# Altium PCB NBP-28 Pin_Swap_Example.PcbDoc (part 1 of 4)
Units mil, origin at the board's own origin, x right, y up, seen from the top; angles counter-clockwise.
Board outline 2716.54 x 4967.15 mil, 10 copper layers (Top Layer, Mid-Layer 1, VCC1V2, Mid-Layer 2, VCC, GND, MidLayer4, VCCINT, Mid-Layer 3, Bottom Layer), stack 81 mil thick; 254 components, 445 nets, 1667 pads, 770 vias.
Unrouted connection lines stored in the file: 611.
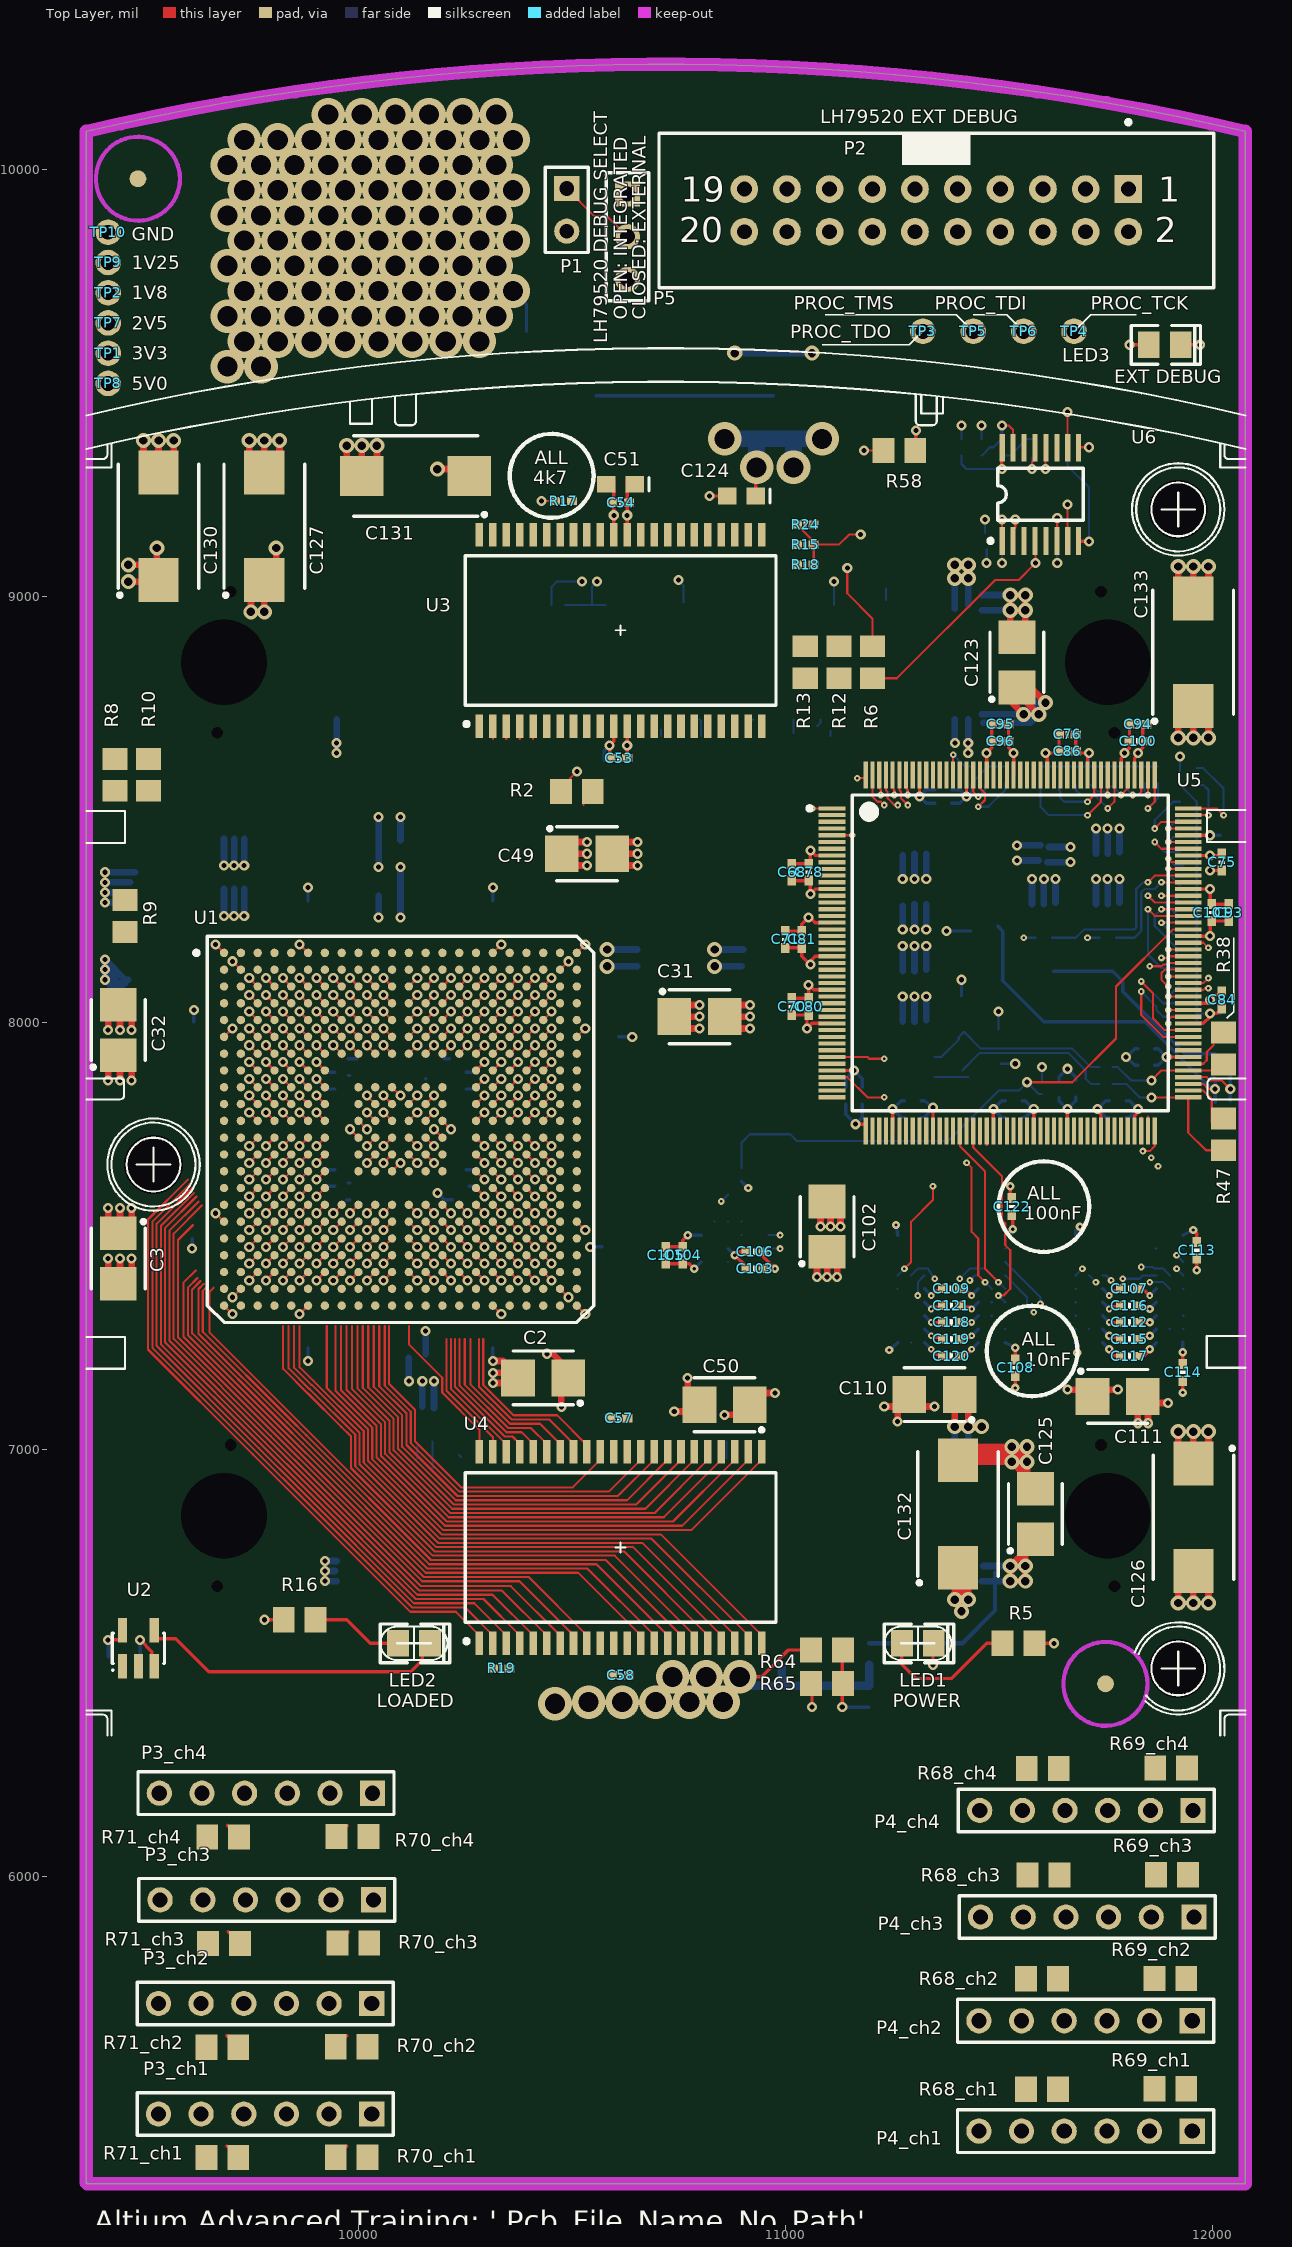
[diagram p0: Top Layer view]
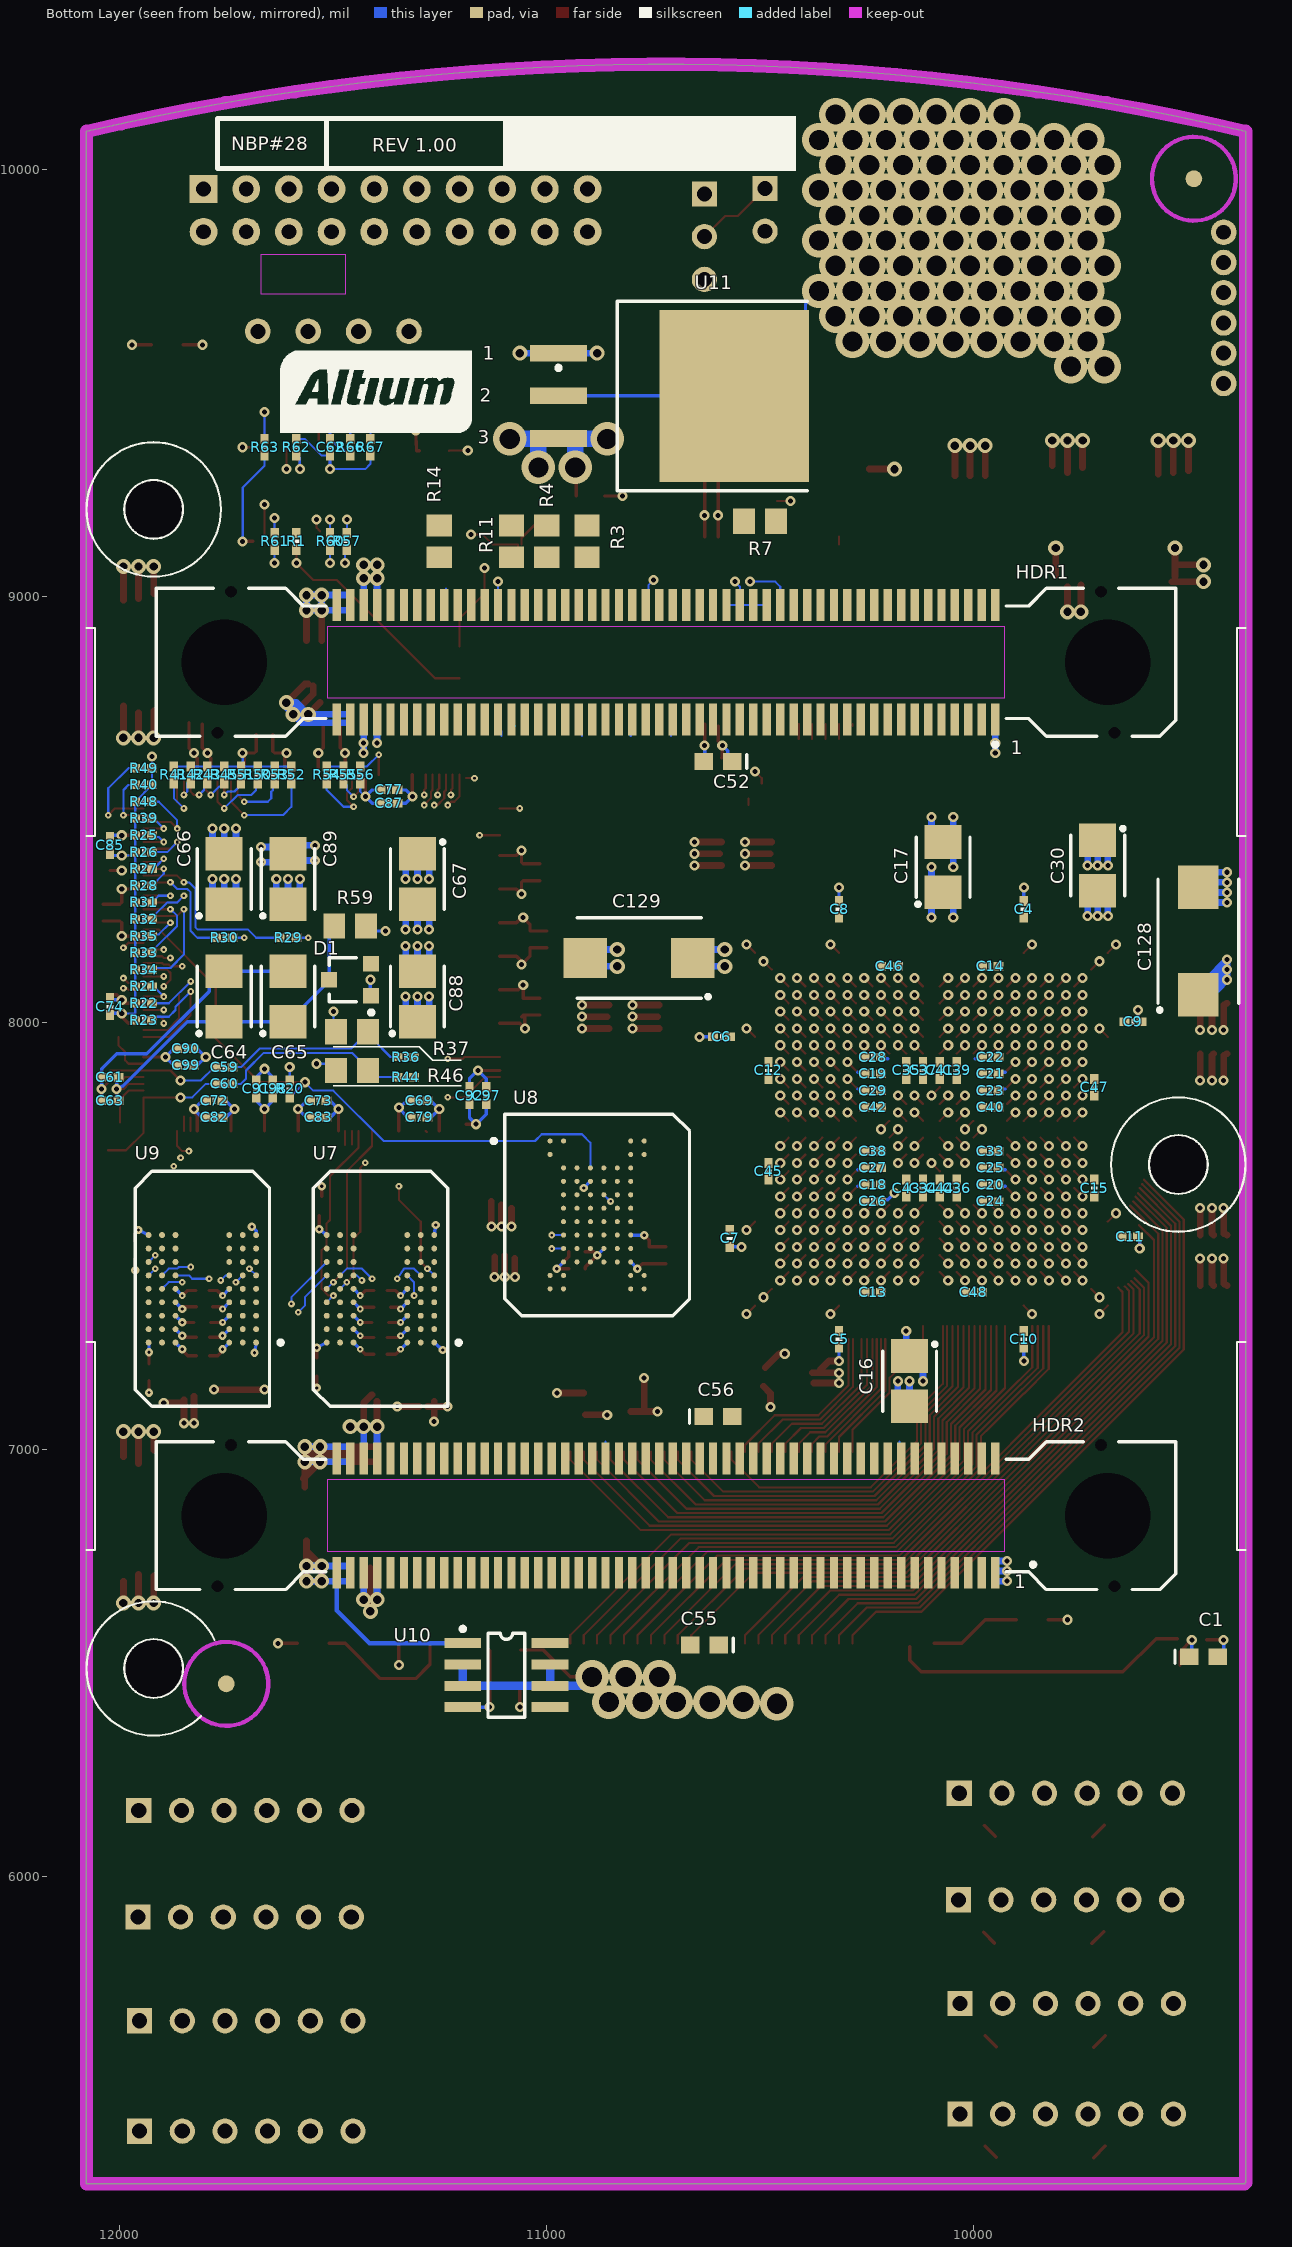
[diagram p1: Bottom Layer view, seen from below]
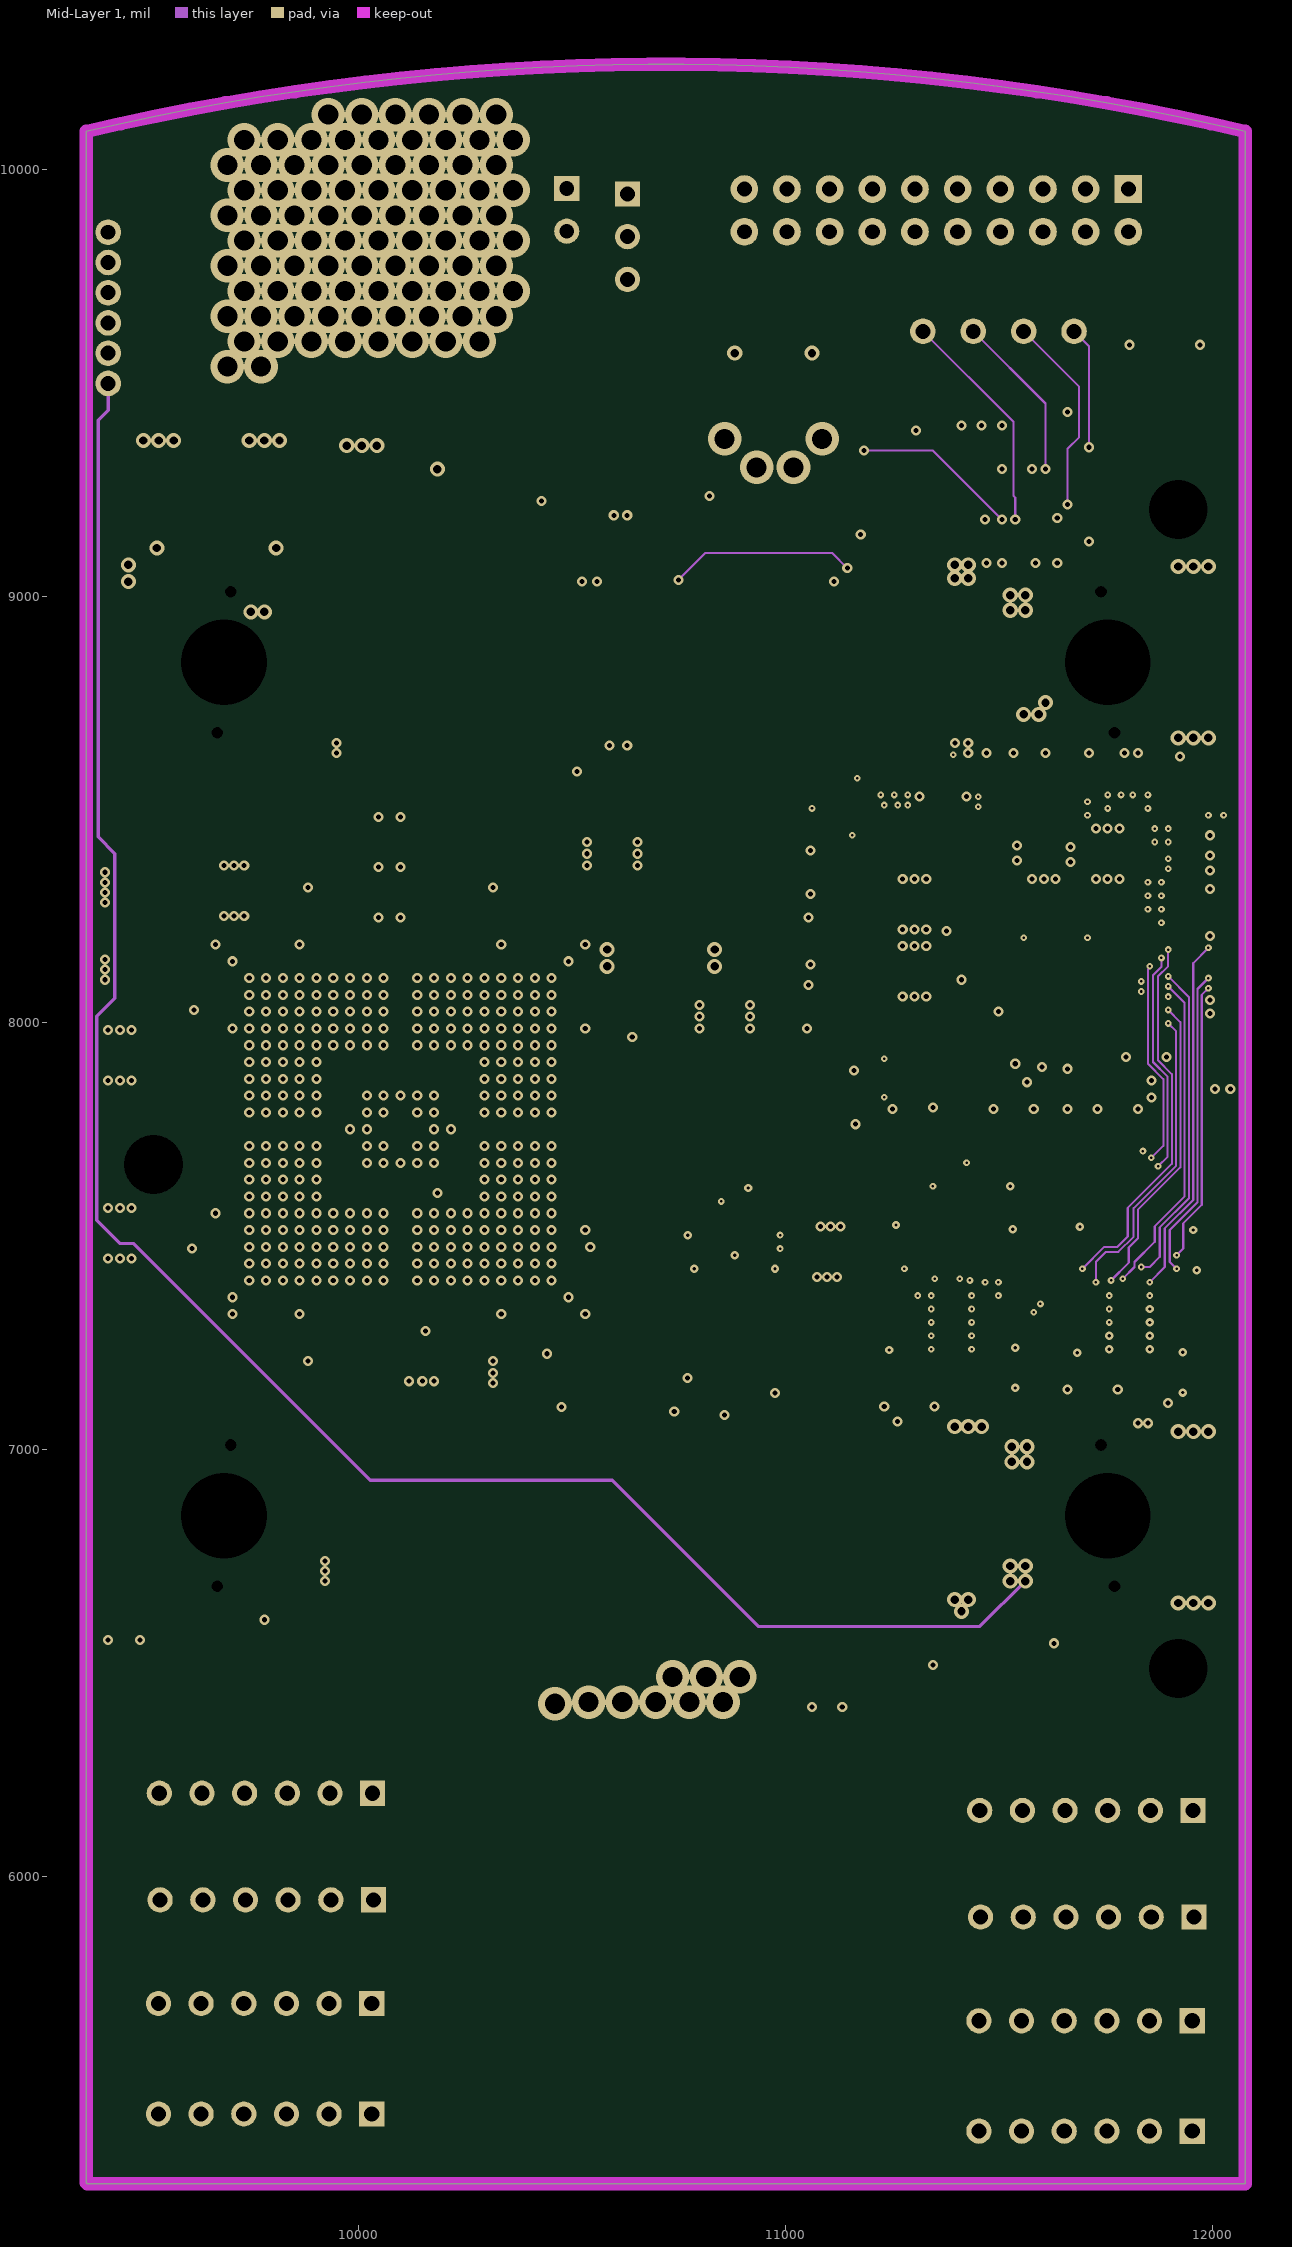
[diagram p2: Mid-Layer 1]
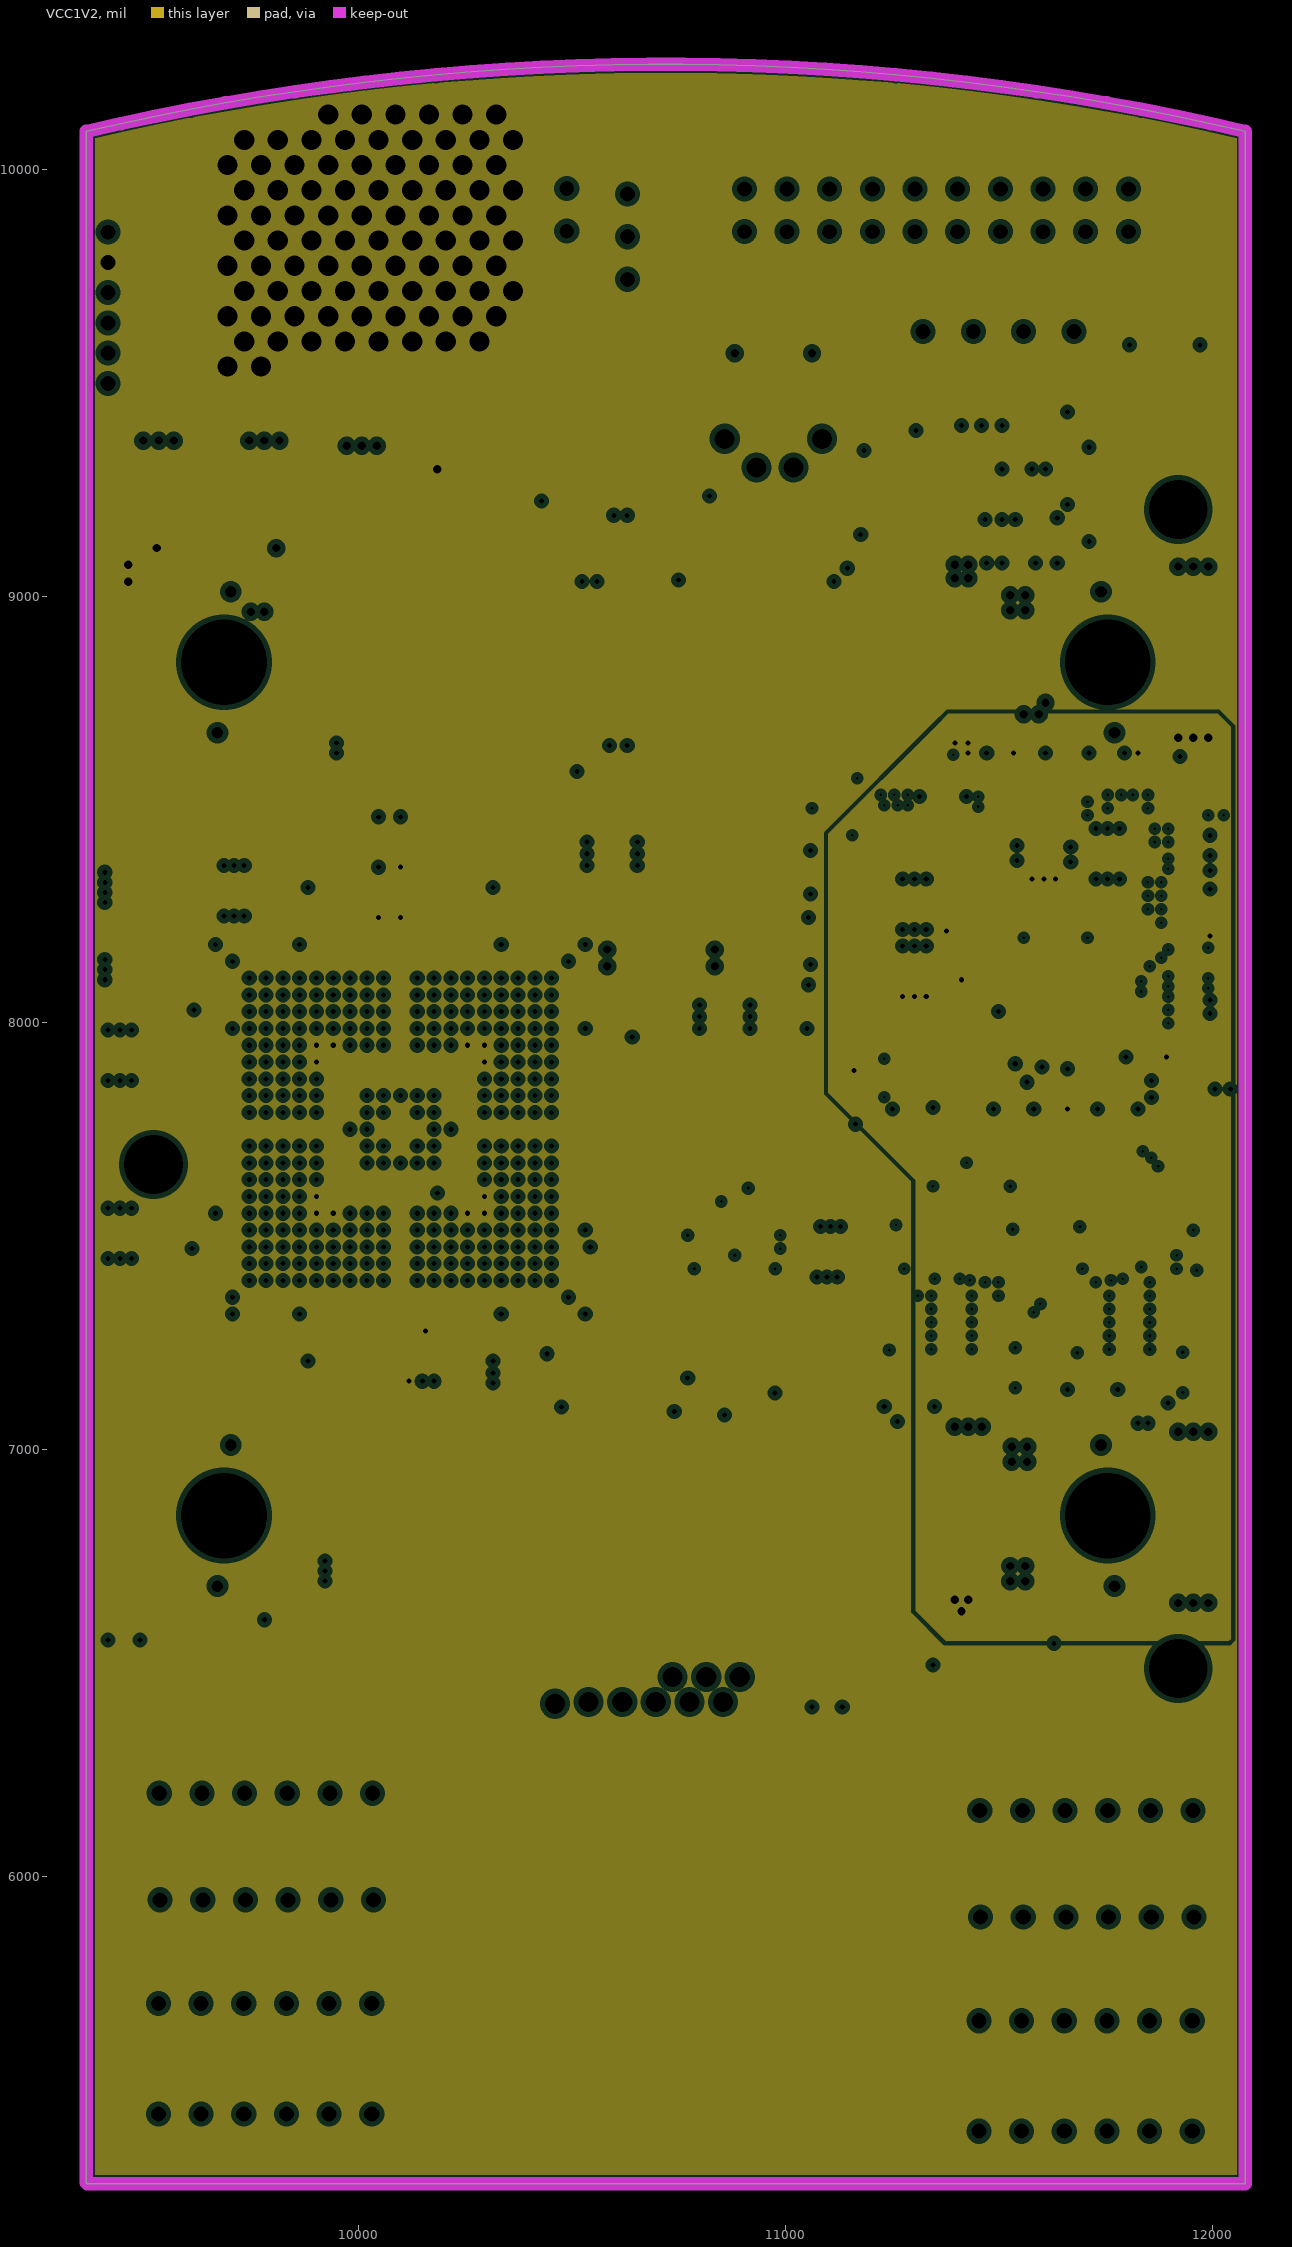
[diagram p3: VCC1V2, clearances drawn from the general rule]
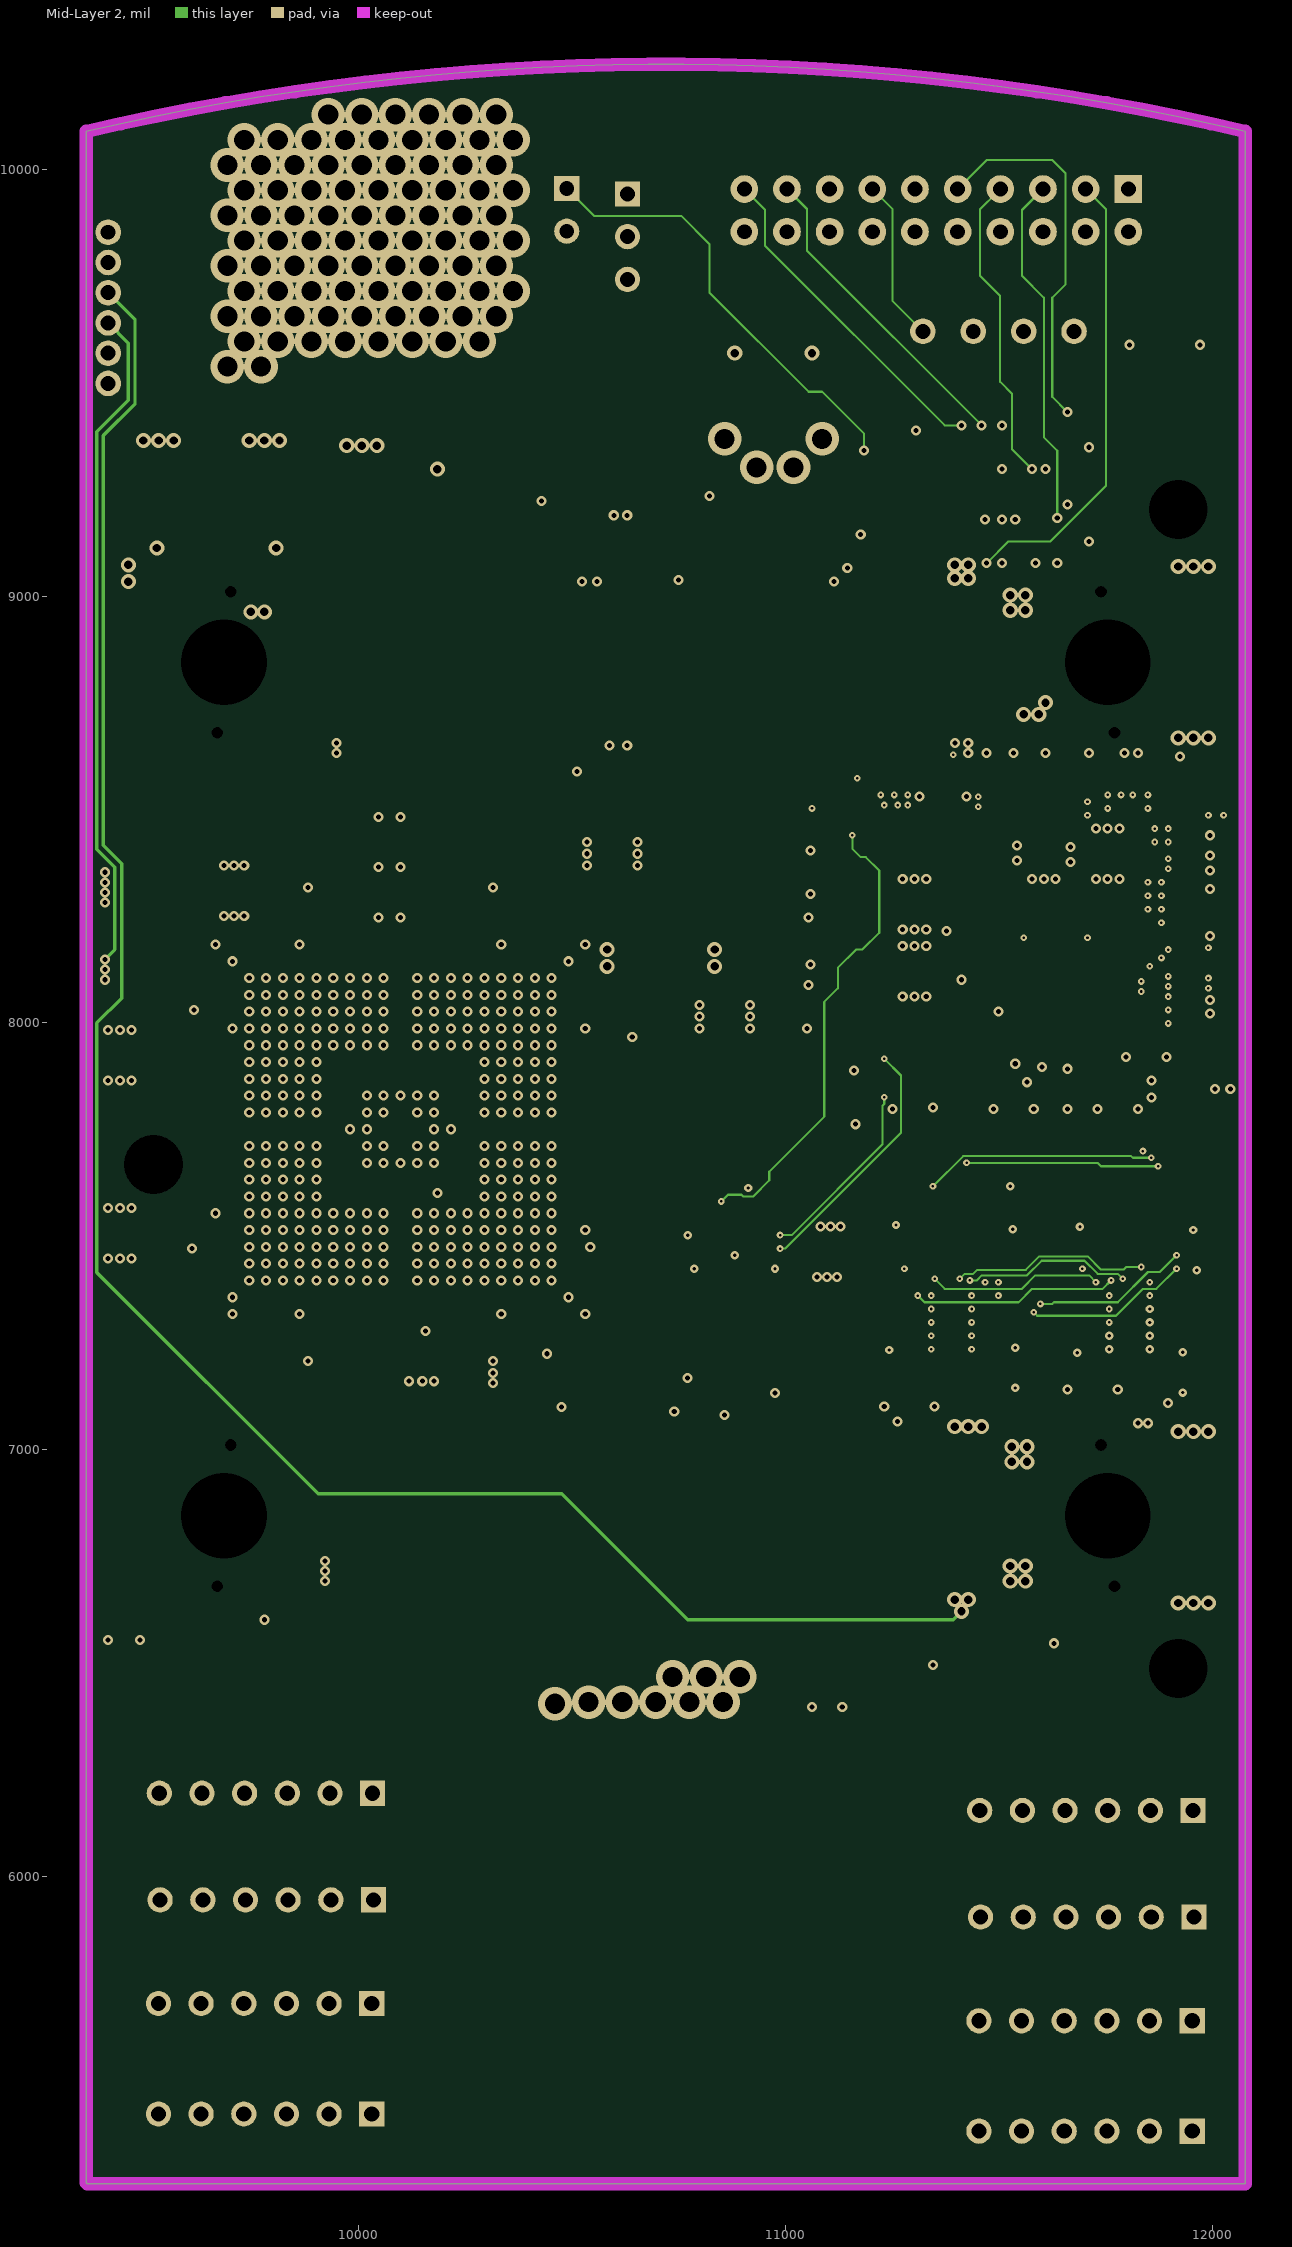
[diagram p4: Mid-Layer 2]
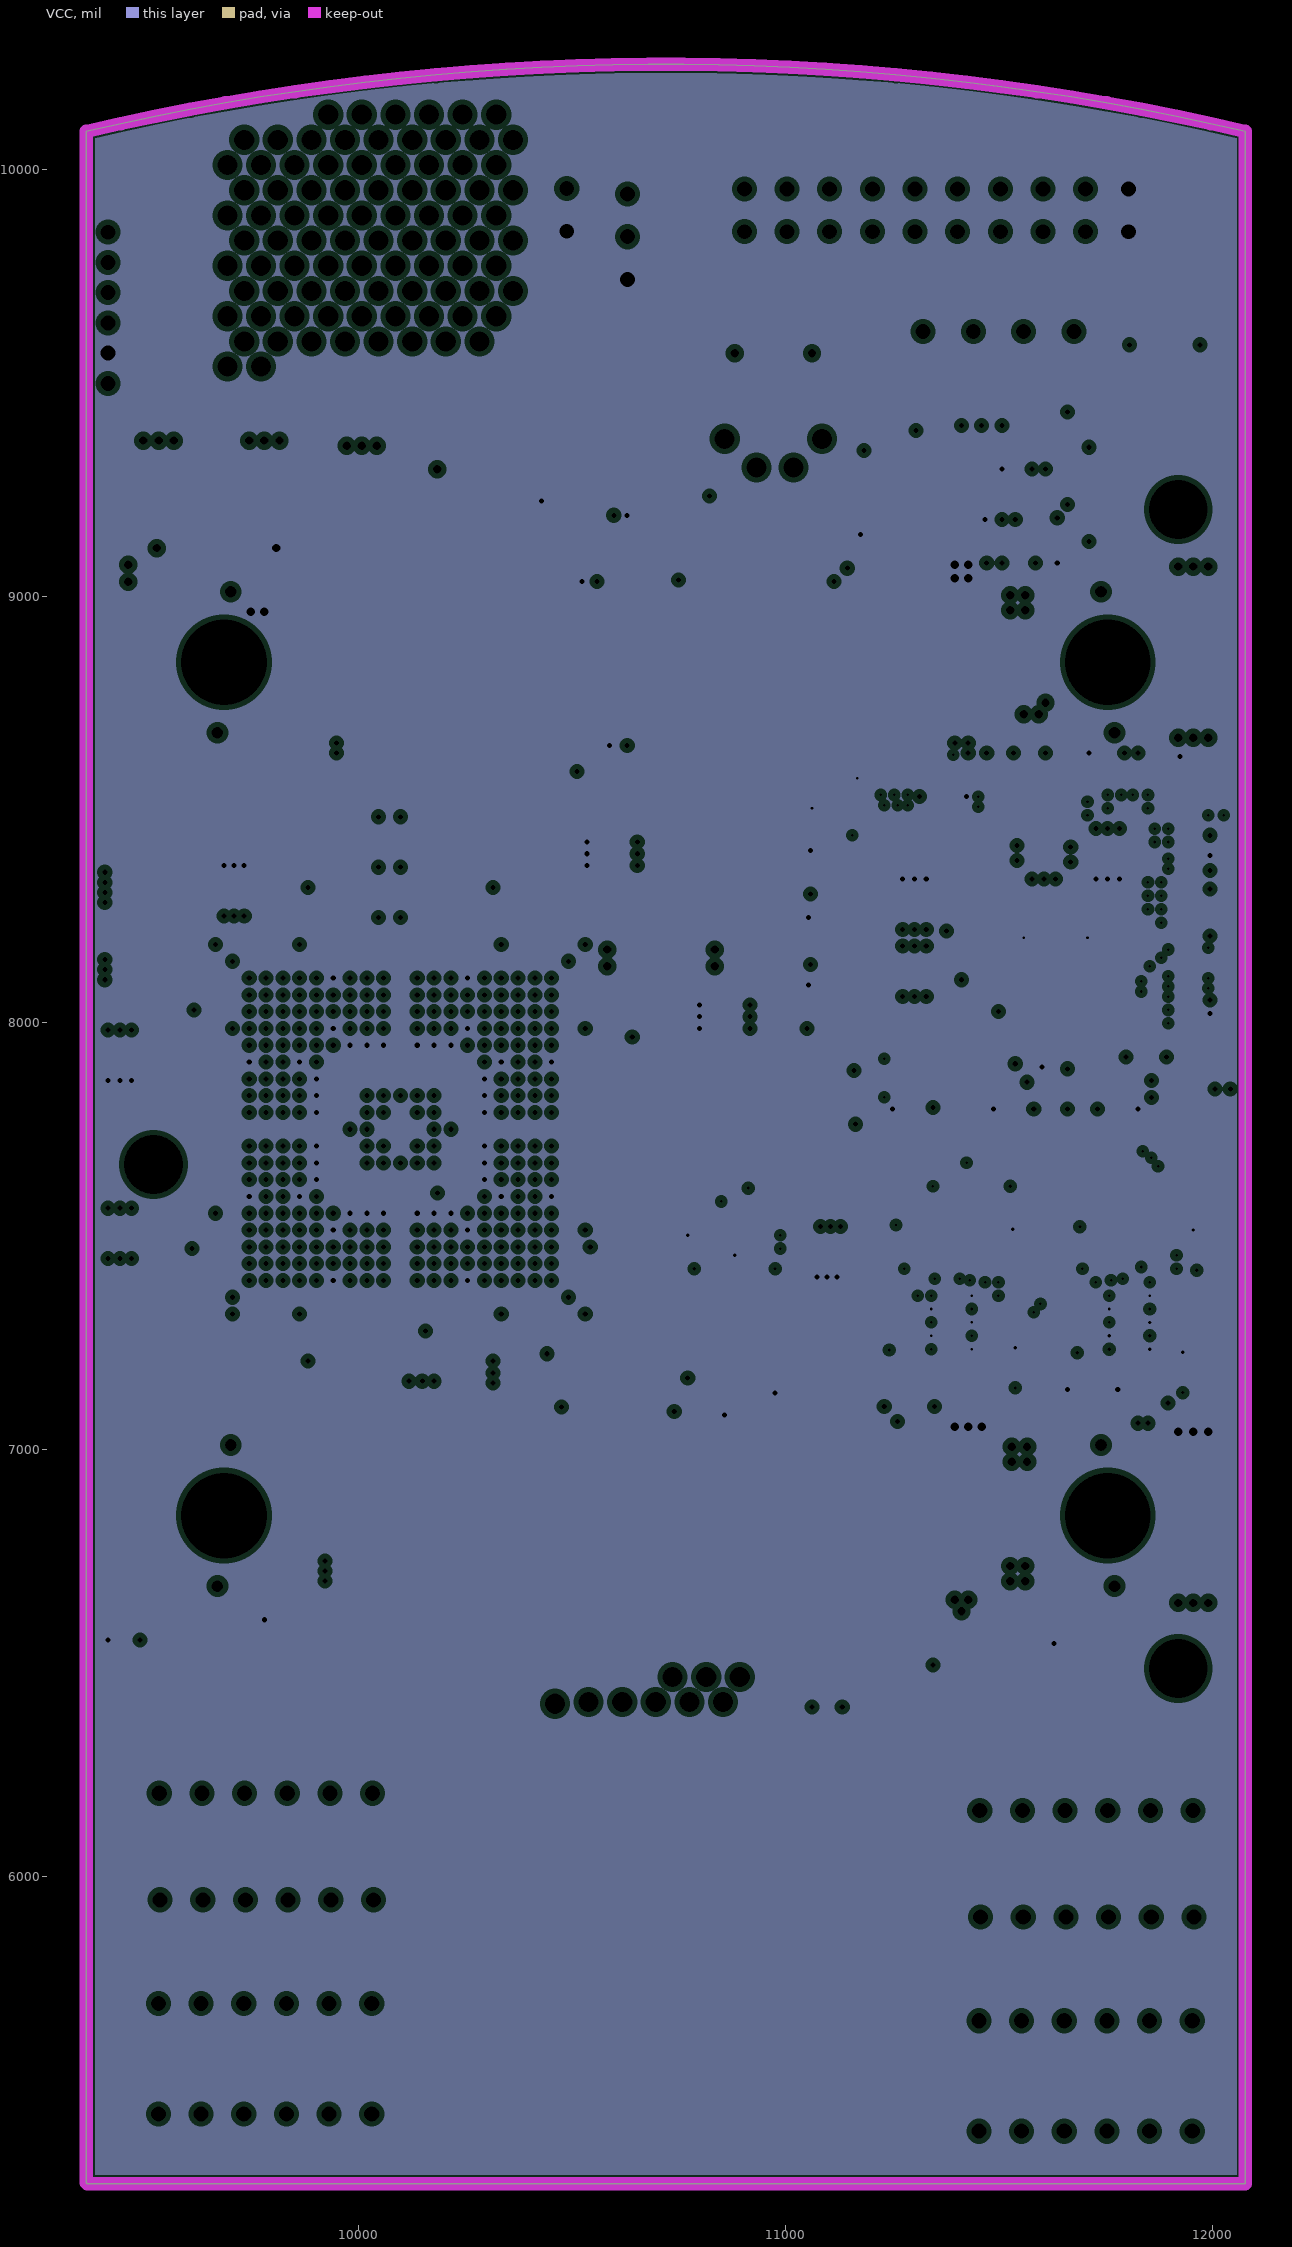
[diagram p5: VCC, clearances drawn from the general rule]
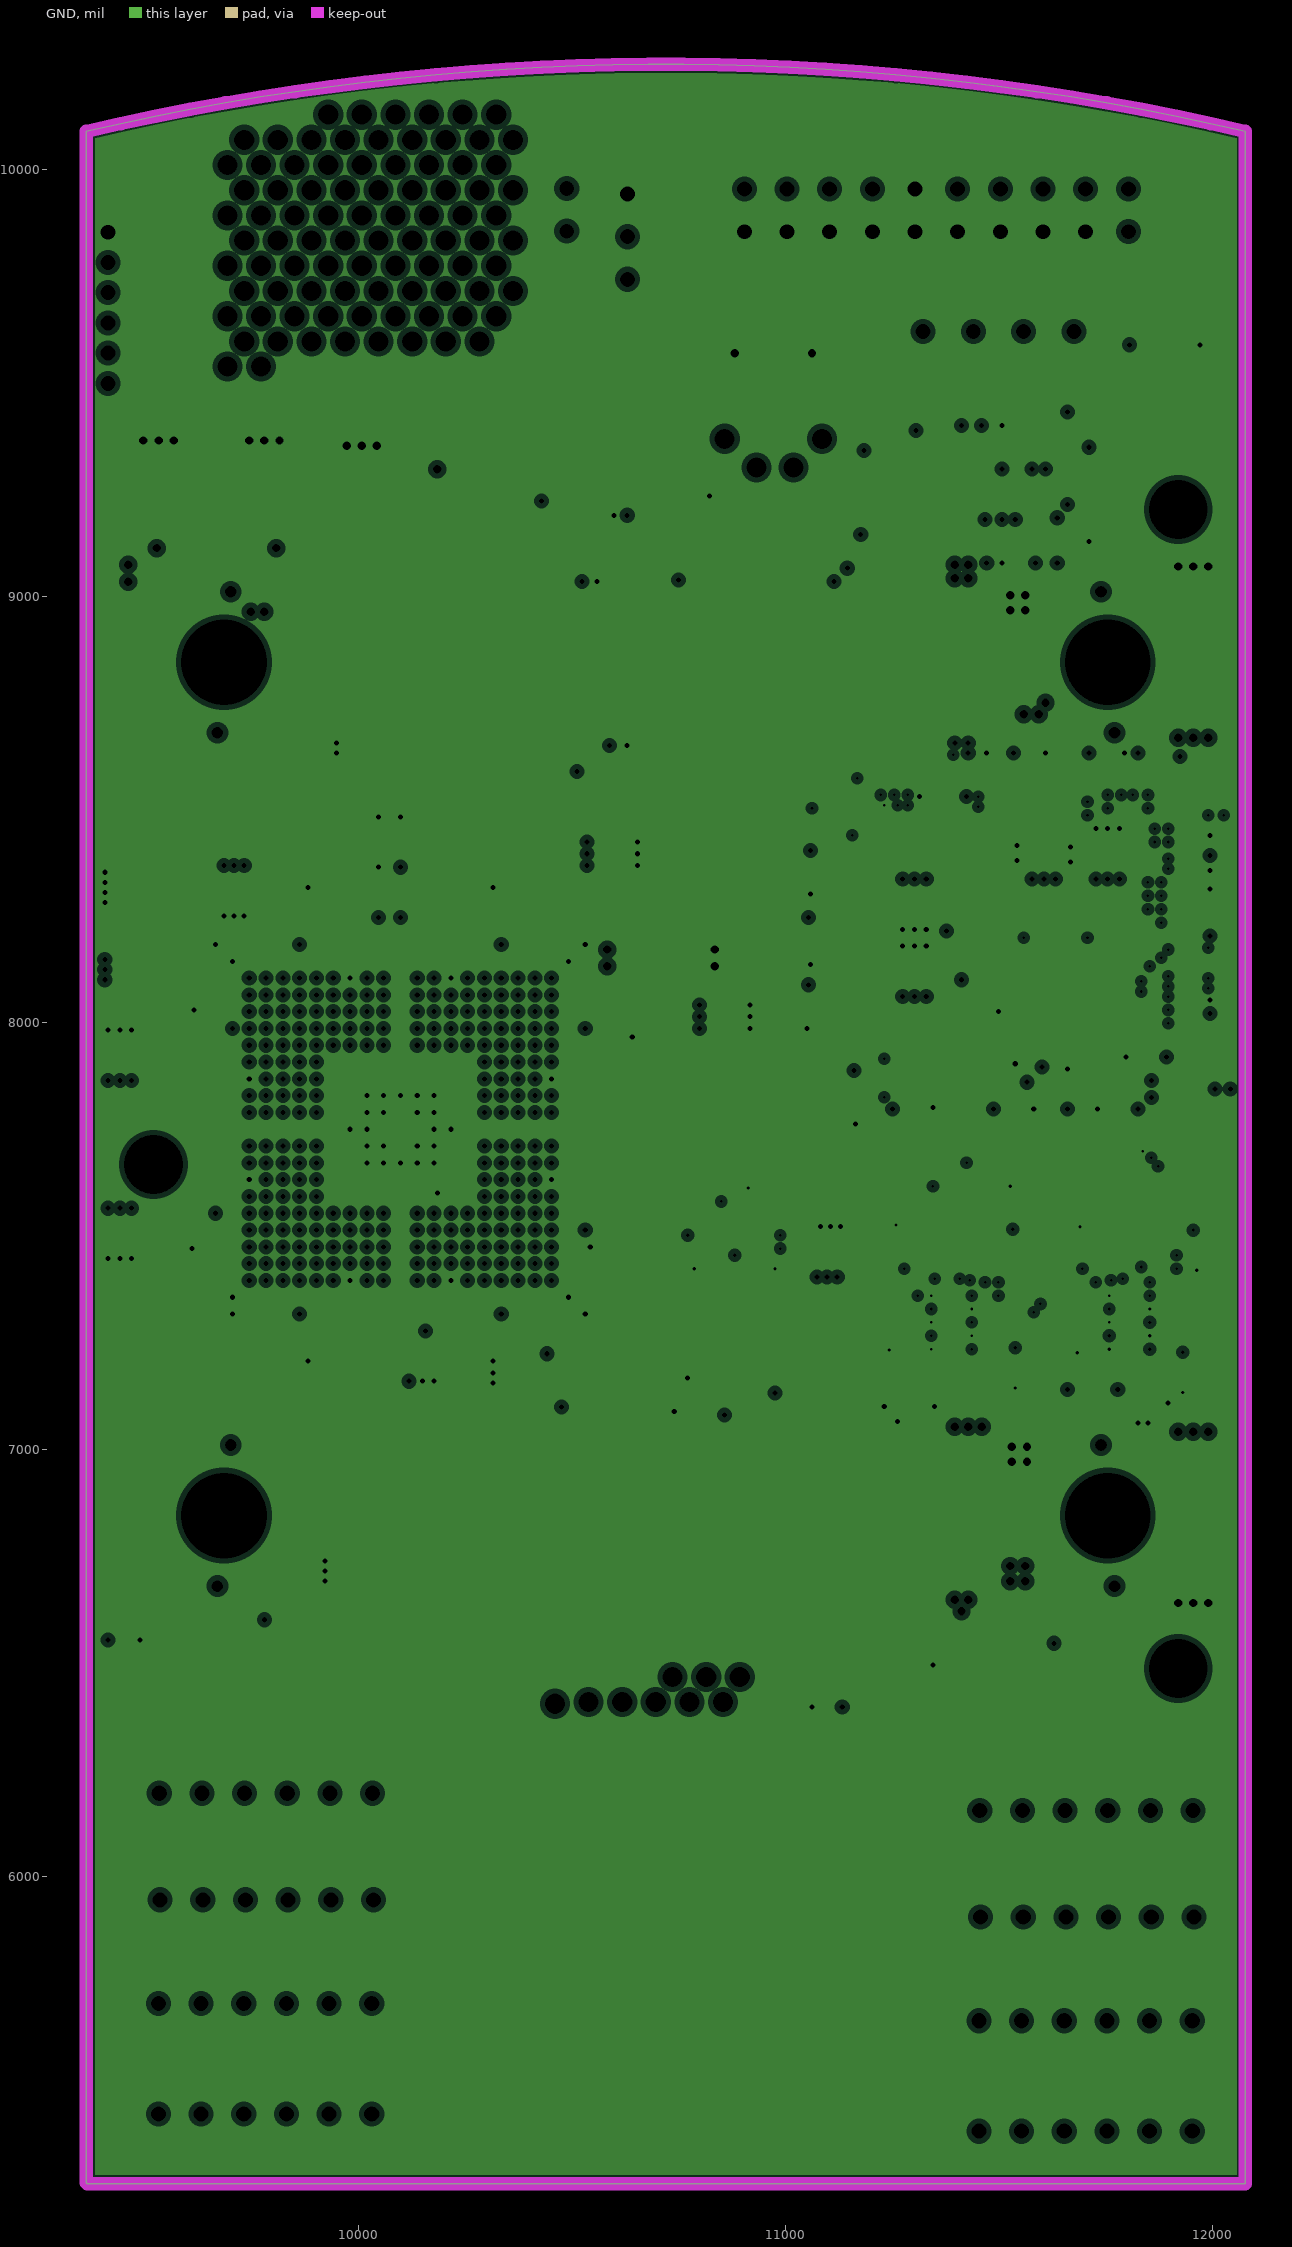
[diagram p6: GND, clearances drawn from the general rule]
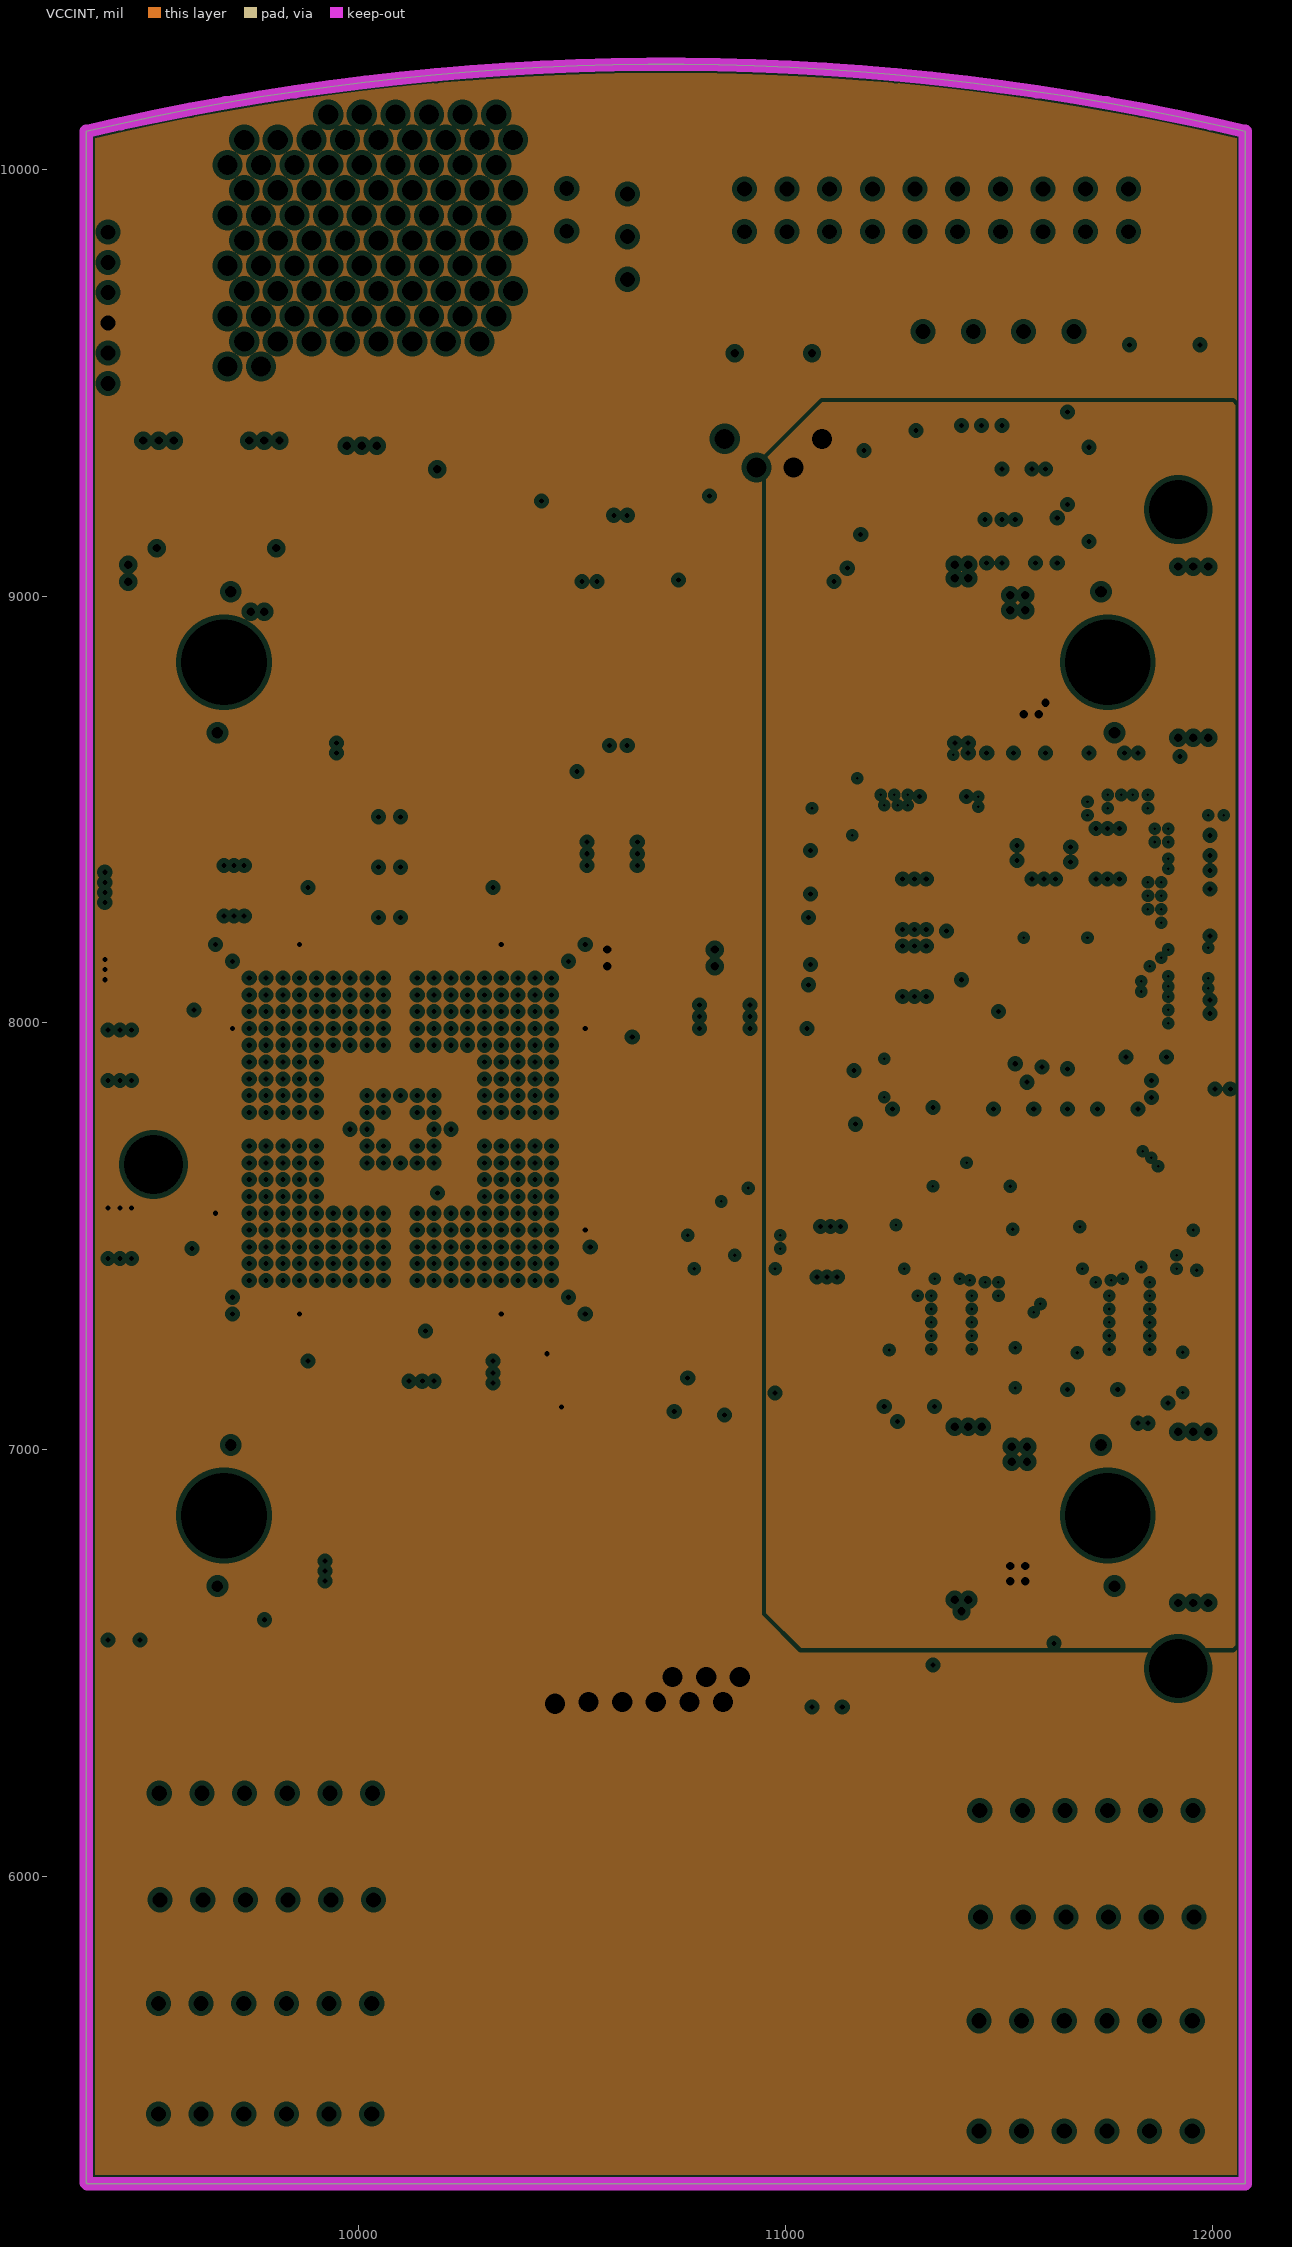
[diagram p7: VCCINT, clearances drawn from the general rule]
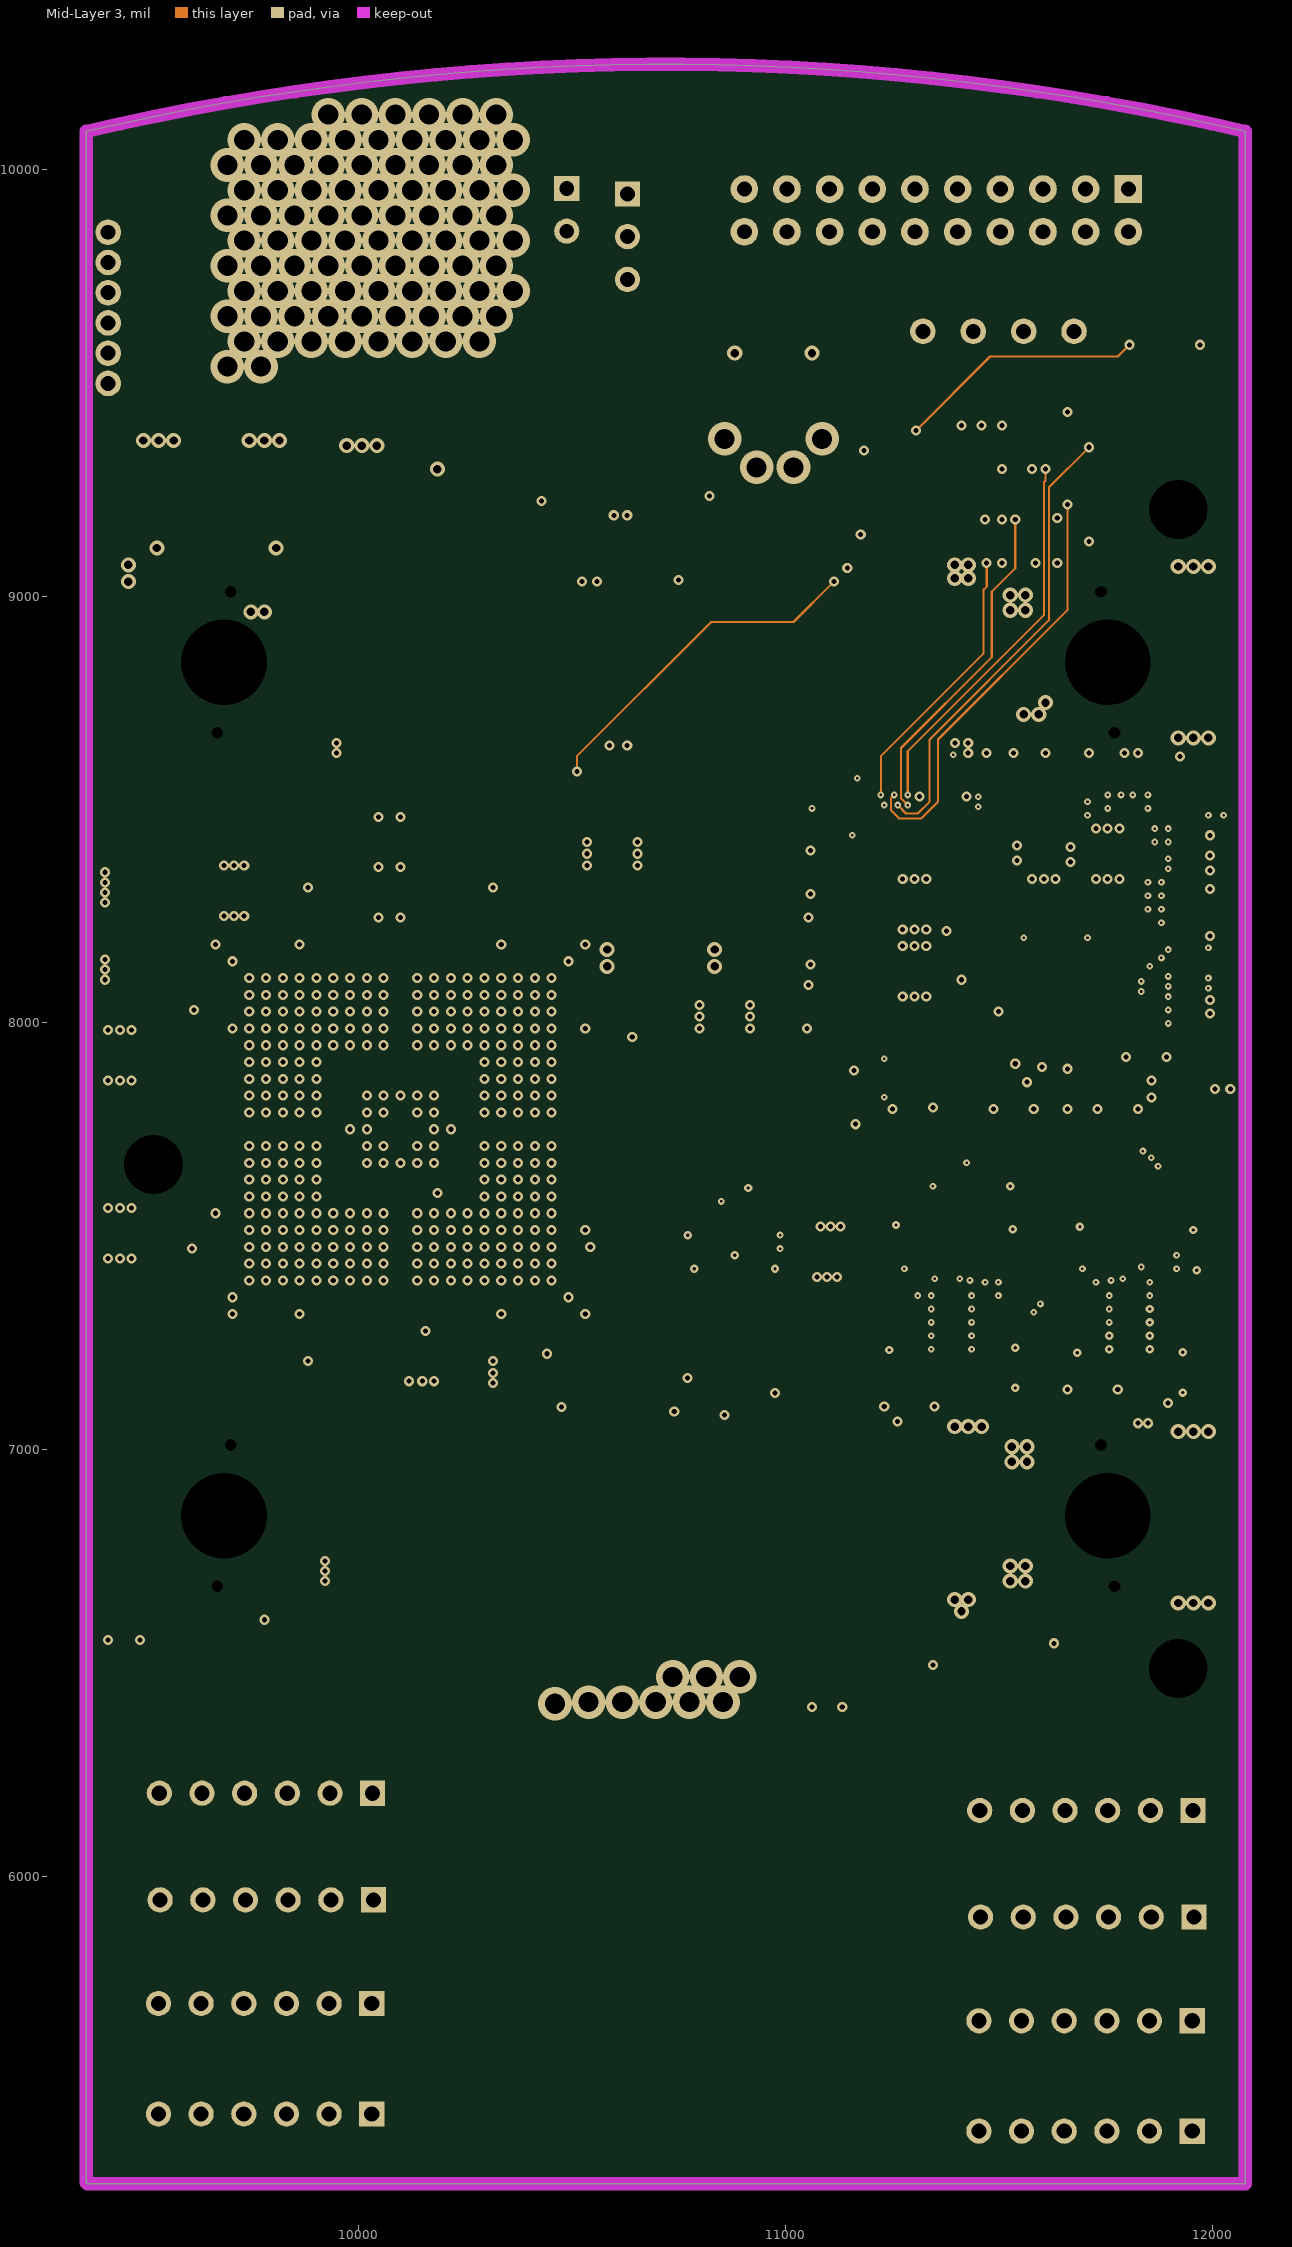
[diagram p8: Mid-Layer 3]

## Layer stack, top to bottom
Top Solder: solder mask 0.4, Solder Resist, Dk 3.5
Top Layer: signal copper 1.4
Dielectric1: core 7, FR-4, Dk 4.8
Mid-Layer 1: signal copper 1.4
Dielectric2: prepreg 8, FR-4, Dk 4.8
VCC1V2: plane copper 1.4, net (Multiple Nets)
Dielectric9: core 7, FR-4, Dk 4.8
Mid-Layer 2: signal copper 1.4
Dielectric3: prepreg 8, FR-4, Dk 4.8
VCC: plane copper 1.4, net VCC3V3
Dielectric8: core 7, FR-4, Dk 4.8
GND: plane copper 1.4, net GND
Dielectric6: prepreg 8, FR-4, Dk 4.8
MidLayer4: signal copper 1.4
Dielectric5: core 7, FR-4, Dk 4.8
VCCINT: plane copper 1.4, net (Multiple Nets)
Dielectric7: prepreg 8, FR-4, Dk 4.8
Mid-Layer 3: signal copper 1.4
Dielectric4: core 7, FR-4, Dk 4.8
Bottom Layer: signal copper 1.4
Bottom Solder: solder mask 0.4, Solder Resist, Dk 3.5

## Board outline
9361.68,5281.7 9361.68,10089.55 cw(c10719.92,4309.99) 12078.19,10089.54 12078.22,10089.55 12078.22,5279.7 9363.68,5279.7

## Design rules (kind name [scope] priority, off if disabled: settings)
Clearance "LQFP Clearance" [isPad and InComponent(U5) vs isPad and InComponent(U5)] p1: gap=5.91 ignorepadtopadclearanceinfootprint=FALSE except(0: Arc-Hole Track-Hole SMDPad-Hole THPad-Hole Via-Hole Fill-Hole Poly-Hole Region-Hole Text-Hole)
Clearance Clearance_Polygons [InPolygon] p2: gap=11.81 ignorepadtopadclearanceinfootprint=FALSE except(0: Arc-Hole Track-Hole SMDPad-Hole THPad-Hole Via-Hole Fill-Hole Poly-Hole Region-Hole Text-Hole)
Clearance "InnerLayer Track-Via Clearance" [OnMid And IsTrack vs IsVia] p3: gap=5 ignorepadtopadclearanceinfootprint=FALSE except(0: Arc-Hole Track-Hole SMDPad-Hole THPad-Hole Via-Hole Fill-Hole Poly-Hole Region-Hole Text-Hole)
Clearance "Via-Via Clearance" [IsVia vs IsVia] p4: gap=7.87 ignorepadtopadclearanceinfootprint=FALSE except(0: Arc-Hole Track-Hole SMDPad-Hole THPad-Hole Via-Hole Fill-Hole Poly-Hole Region-Hole Text-Hole)
Clearance "Pad-Pad Clearance Same Net" [IsPad vs IsPad] p5: gap=10 ignorepadtopadclearanceinfootprint=FALSE except(0: Arc-Hole Track-Hole SMDPad-Hole THPad-Hole Via-Hole Fill-Hole Poly-Hole Region-Hole Text-Hole)
Clearance "Via-Pad Clearance" [IsVia vs IsPad] p6: gap=5 ignorepadtopadclearanceinfootprint=FALSE except(0: Arc-Hole Track-Hole SMDPad-Hole THPad-Hole Via-Hole Fill-Hole Poly-Hole Region-Hole Text-Hole)
Clearance "General Clearance" [All] p7: gap=5 ignorepadtopadclearanceinfootprint=FALSE except(0: Arc-Hole Track-Hole SMDPad-Hole THPad-Hole Via-Hole Fill-Hole Poly-Hole Region-Hole Text-Hole)
ComponentClearance [All] p1 off: gap=7.87 collisioncheckmode=3 verticalgap=10 showdistances=FALSE
DiffPairsRouting [All] p1: maxlimit=10 minlimit=10 mostfreqgap=10 toplayer_minwidth=15 toplayer_maxwidth=15 toplayer_prefwidth=15 midlayer1_minwidth=15 midlayer1_maxwidth=15 midlayer1_prefwidth=15 midlayer2_minwidth=15 midlayer2_maxwidth=15 midlayer2_prefwidth=15 midlayer3_minwidth=15 midlayer3_maxwidth=15 midlayer3_prefwidth=15 midlayer4_minwidth=15 midlayer4_maxwidth=15 midlayer4_prefwidth=15 bottomlayer_minwidth=15 bottomlayer_maxwidth=15 bottomlayer_prefwidth=15 maxuncoupledlength=500
FabricationTestPointUsage TestPointUsage [All] p1 off: valid=0 allowmultiple=FALSE
FabricationTestpoint Testpoint [All] p1 off: side=3 testpointundercomponent=TRUE minsize=40 maxsize=100 preferedsize=60 minholesize=0 maxholesize=40 preferedholesize=32 testpointgrid=1 allowsidetop=TRUE allowsidebottom=TRUE usegrid=TRUE gridtolerance=0.01
HoleSize [All] p1: absolutevalues=TRUE maxlimit=204.72 minlimit=5.91 maxpercent=80.000 minpercent=20.000
MinimumSolderMaskSliver [All] p1: minsoldermaskwidth=5
PlaneClearance [All] p1: clearance=11.81
PlaneConnect [All] p1: planeconnectstyle=Direct reliefexpansion=19.68 reliefentries=4 reliefconductorwidth=9.84 reliefairgap=9.84
PolygonConnect "PolygonConnect - High Current" [InNet('+5V') or InNet(VCC2V5)] p1: connectstyle=Direct reliefconductorwidth=10 reliefentries=4 polygonreliefangle="90 Angle" airgapwidth=10
PolygonConnect "PolygonConnect - Heatsink" [(HasFootprint('TO-263') AND InNet('VCC1V2'))] p2: connectstyle=Direct reliefconductorwidth=10 reliefentries=4 polygonreliefangle="90 Angle" airgapwidth=10
PolygonConnect [All] p3: connectstyle=Relief reliefconductorwidth=11.81 reliefentries=4 polygonreliefangle="90 Angle" airgapwidth=10
RoomDefinition ch1 [InComponentClass('ch1')] p1: confinementstyle=ConfineIn formatcopy=TRUE lockcomponents=FALSE outline 9402.11,5304.34 12053.01,5304.34 12053.01,5538.53 9402.11,5538.53
RoomDefinition ch2 [InComponentClass('ch2')] p2: confinementstyle=ConfineIn formatcopy=TRUE lockcomponents=FALSE outline 9402.11,5554.93 12053.01,5554.93 12053.01,5800.27 9402.11,5800.27
RoomDefinition ch3 [InComponentClass('ch3')] p3: confinementstyle=ConfineIn formatcopy=TRUE lockcomponents=FALSE outline 9406.05,5805.52 12056.94,5805.52 12056.94,6039.71 9406.05,6039.71
RoomDefinition ch4 [InComponentClass('ch4')] p4: confinementstyle=ConfineIn formatcopy=TRUE lockcomponents=FALSE outline 9404.08,6056.11 12054.98,6056.11 12054.98,6290.3 9404.08,6290.3
RoutingVias [All] p1: holewidth=11.81 width=23.62 viastyle="Through Hole" minholewidth=5.91 minwidth=15.75 maxholewidth=28 maxwidth=50
SilkToSolderMaskClearance SilkscreenOverComponentPads [IsPad] p1: minsilkscreentomaskgap=5 clearancetoexposedcopper=TRUE
SolderMaskExpansion SolderMaskExpansion_0402 [HasFootprint('CC1005-0402')] p1: expansion=2.95 istentingtop=FALSE
SolderMaskExpansion SolderMaskExpansion_Vias [IsVia] p2: expansion=-25.59 istentingtop=FALSE
SolderMaskExpansion [All] p3: expansion=3.94 istentingtop=FALSE
SupplyNets SupplyNets_GND [InNet('GND')] p1: voltage=0,000
SupplyNets SupplyNets_3V3 [InNet('VCC3V3')] p2: voltage=3,000
SupplyNets SupplyNets_2V5 [InNet('VCC2V5')] p3: voltage=2,000
SupplyNets SupplyNets_1V8 [InNet('VCC1V8')] p4: voltage=1,000
SupplyNets SupplyNets_1V2 [InNet('VCC1V2')] p5: voltage=1,000
SupplyNets SupplyNets_5V [InNet('+5V')] p6: voltage=5,000
Width [All] p1: maxlimit=98.42 minlimit=5 preferedwidth=5
21 further rules are at their usual default settings.

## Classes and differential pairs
channel class Multi-channel_diff-pairs: ch1 ch2 ch3 ch4
component class ch1: P3_ch1 P4_ch1 R68_ch1 R69_ch1 R70_ch1 R71_ch1
component class ch2: P3_ch2 P4_ch2 R68_ch2 R69_ch2 R70_ch2 R71_ch2
component class ch3: P3_ch3 P4_ch3 R68_ch3 R69_ch3 R70_ch3 R71_ch3
component class ch4: P3_ch4 P4_ch4 R68_ch4 R69_ch4 R70_ch4 R71_ch4
component class TOP_SHEET: C123 C124 C125 C126 C127 C128 C129 C130 C131 C132 C133 R64 R65 TP7 TP8 TP9 TP10 U10 U11
component class U_FPGA_RAM: C49 C50 C51 C52 C53 C54 C55 C56 C57 C58 U3 U4
component class U_FPGA: C1 C2 C3 C4 C5 C6 C7 C8 C9 C10 C11 C12 C13 C14 C15 C16 C17 C18 C19 C20 C21 C22 C23 C24 C25 C26 C27 C28 C29 C30 C31 C32 C33 C34 C35 C36 C37 C38 C39 C40 C41 C42 C43 C44 C45 C46 C47 C48 HDR1 HDR2 LED1 LED2 R1 R2 R3 R4 R5 R6 R7 R8 R9 R10 R11 R12 R13 R14 R15 R16 R17 R18 R19 TP1 TP2 U1 U2
component class U_PROCESSOR_MEMORIES: C102 C103 C104 C105 C106 C107 C108 C109 C110 C111 C112 C113 C114 C115 C116 C117 C118 C119 C120 C121 C122 U7 U8 U9
component class U_PROCESSOR: C59 C60 C61 C62 C63 C64 C65 C66 C67 C68 C69 C70 C71 C72 C73 C74 C75 C76 C77 C78 C79 C80 C81 C82 C83 C84 C85 C86 C87 C88 C89 C90 C91 C92 C93 C94 C95 C96 C97 C98 C99 C100 C101 D1 LED3 P1 P2 P5 R20 R21 R22 R23 R24 R25 R26 R27 R28 R29 R30 R31 R32 R33 R34 R35 R36 R37 R38 R39 R40 R41 R42 R43 R44 R45 R46 R47 R48 R49 R50 R51 R52 R53 R54 R55 R56 R57 R58 R59 R60 R61 R62 R63 R66 R67 TP3 TP4 TP5 TP6 U5 U6
net class A[25..0]: A0 A1 A2 A3 A4 A5 A6 A7 A8 A9 A10 A11 A12 A13 A14 A15 A16 A17 A18 A19 A20 A21 A22 A23 A24 A25
net class D[31..0]: D0 D1 D2 D3 D4 D5 D6 D7 D8 D9 D10 D11 D12 D13 D14 D15 D16 D17 D18 D19 D20 D21 D22 D23 D24 D25 D26 D27 D28 D29 D30 D31
net class INT[4..0]: INT0 INT1 INT2 INT3 INT4
net class NBLE[3..0]: NBLE0 NBLE1 NBLE2 NBLE3
net class NCS[5..0]: NCS0 NCS1 NCS2 NCS3 NCS4 NCS5
net class SDRAM_DQM[3..0]: SDRAM_DQM0 SDRAM_DQM1 SDRAM_DQM2 SDRAM_DQM3
net class SRAM0_A[18..0]: SRAM0_A0 SRAM0_A1 SRAM0_A2 SRAM0_A3 SRAM0_A4 SRAM0_A5 SRAM0_A6 SRAM0_A7 SRAM0_A8 SRAM0_A9 SRAM0_A10 SRAM0_A11 SRAM0_A12 SRAM0_A13 SRAM0_A14 SRAM0_A15 SRAM0_A16 SRAM0_A17 SRAM0_A18
net class SRAM0_D[15..0]: SRAM0_D0 SRAM0_D1 SRAM0_D2 SRAM0_D3 SRAM0_D4 SRAM0_D5 SRAM0_D6 SRAM0_D7 SRAM0_D8 SRAM0_D9 SRAM0_D10 SRAM0_D11 SRAM0_D12 SRAM0_D13 SRAM0_D14 SRAM0_D15
net class SRAM1_A[18..0]: SRAM1_A0 SRAM1_A1 SRAM1_A2 SRAM1_A3 SRAM1_A4 SRAM1_A5 SRAM1_A6 SRAM1_A7 SRAM1_A8 SRAM1_A9 SRAM1_A10 SRAM1_A11 SRAM1_A12 SRAM1_A13 SRAM1_A14 SRAM1_A15 SRAM1_A16 SRAM1_A17 SRAM1_A18
net class SRAM1_D[15..0]: SRAM1_D0 SRAM1_D1 SRAM1_D2 SRAM1_D3 SRAM1_D4 SRAM1_D5 SRAM1_D6 SRAM1_D7 SRAM1_D8 SRAM1_D9 SRAM1_D10 SRAM1_D11 SRAM1_D12 SRAM1_D13 SRAM1_D14 SRAM1_D15
differential pair DIFF_RX_ch1: +DIFF_RX_ch1_P -DIFF_RX_ch1_N
differential pair DIFF_RX_ch2: +DIFF_RX_ch2_P -DIFF_RX_ch2_N
differential pair DIFF_RX_ch3: +DIFF_RX_ch3_P -DIFF_RX_ch3_N
differential pair DIFF_RX_ch4: +DIFF_RX_ch4_P -DIFF_RX_ch4_N
differential pair DIFF_TX_ch1: +DIFF_TX_ch1_P -DIFF_TX_ch1_N
differential pair DIFF_TX_ch2: +DIFF_TX_ch2_P -DIFF_TX_ch2_N
differential pair DIFF_TX_ch3: +DIFF_TX_ch3_P -DIFF_TX_ch3_N
differential pair DIFF_TX_ch4: +DIFF_TX_ch4_P -DIFF_TX_ch4_N

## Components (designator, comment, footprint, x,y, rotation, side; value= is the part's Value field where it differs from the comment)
C1 "220nF 10V" CAPC1608 9460.11,6514.74 r180 bottom
C2 "10uF 16V" CAPC3528 10432.55,7168.29 r180 top
C3 "10uF 16V" CAPC3528 9436.48,7447.81 r270 top
C4 "0.1uF 16V" CAPC1005 9881.37,8266.71 r90 bottom
C5 "0.1uF 16V" CAPC1005 10314.44,7258.84 r270 bottom
C6 "10nF 16V" CAPC1005 10590.03,7967.5 r0 bottom
C7 "10nF 16V" CAPC1005 10570.34,7495.06 r270 bottom
C8 "10nF 16V" CAPC1005 10314.44,8266.71 r90 bottom
C9 "10nF 16V" CAPC1005 9625.46,8002.93 r180 bottom
C10 "10nF 16V" CAPC1005 9881.37,7258.84 r270 bottom
C11 "10nF 16V" CAPC1005 9633.33,7499 r180 bottom
C12 "0.1uF 16V" CAPC1005 10479.79,7888.76 r270 bottom
C13 "0.1uF 16V" CAPC1005 10235.7,7369.07 r180 bottom
C14 "0.1uF 16V" CAPC1005 9960.11,8132.85 r0 bottom
C15 "0.1uF 16V" CAPC1005 9716.01,7613.17 r90 bottom
C16 "10uF 16V" CAPC3528 10149.08,7160.41 r270 bottom
C17 "10uF 16V" CAPC3528 10070.34,8365.14 r90 bottom
C18 "0.1uF 16V" CAPC1005 10235.7,7621.04 r180 bottom
C19 "0.1uF 16V" CAPC1005 10235.7,7880.89 r180 bottom
C20 "0.1uF 16V" CAPC1005 9960.11,7621.04 r0 bottom
C21 "0.1uF 16V" CAPC1005 9960.11,7880.89 r0 bottom
C22 "10nF 16V" CAPC1005 9960.11,7920.26 r0 bottom
C23 "10nF 16V" CAPC1005 9960.11,7841.52 r0 bottom
C24 "10nF 16V" CAPC1005 9960.11,7581.67 r0 bottom
C25 "10nF 16V" CAPC1005 9960.11,7660.41 r0 bottom
C26 "10nF 16V" CAPC1005 10235.7,7581.67 r180 bottom
C27 "10nF 16V" CAPC1005 10235.7,7660.41 r180 bottom
C28 "10nF 16V" CAPC1005 10235.7,7920.26 r180 bottom
C29 "10nF 16V" CAPC1005 10235.7,7841.52 r180 bottom
C30 "10uF 16V" CAPC3528 9708.14,8369.07 r270 bottom
C31 "10uF 16V" CAPC3528 10798.69,8014.74 r0 top
C32 "10uF 16V" CAPC3528 9436.48,7983.25 r90 top
C33 "0.1uF 16V" CAPC1005 9960.11,7699.78 r0 bottom
C34 "0.1uF 16V" CAPC1005 10117.59,7613.17 r90 bottom
C35 "0.1uF 16V" CAPC1005 10156.96,7888.76 r270 bottom
C36 "0.1uF 16V" CAPC1005 10038.85,7613.17 r90 bottom
C37 "10nF 16V" CAPC1005 10117.59,7888.76 r270 bottom
C38 "10nF 16V" CAPC1005 10235.7,7699.78 r180 bottom
C39 "10nF 16V" CAPC1005 10038.85,7888.76 r270 bottom
C40 "10nF 16V" CAPC1005 9960.11,7802.15 r0 bottom
C41 "0.1uF 16V" CAPC1005 10078.22,7888.76 r270 bottom
C42 "0.1uF 16V" CAPC1005 10235.7,7802.15 r180 bottom
C43 "10nF 16V" CAPC1005 10156.96,7613.17 r90 bottom
C44 "10nF 16V" CAPC1005 10078.22,7613.17 r90 bottom
C45 "10nF 16V" CAPC1005 10479.79,7652.54 r90 bottom
C46 "10nF 16V" CAPC1005 10196.33,8132.85 r180 bottom
C47 "10nF 16V" CAPC1005 9716.01,7849.39 r270 bottom
C48 "10nF 16V" CAPC1005 9999.48,7369.07 r0 bottom
C49 "10uF 16V" CAPC3528 10534.91,8396.63 r0 top
C50 "10uF 16V" CAPC3528 10857.74,7105.3 r180 top
C51 "220nF 10V" CAPC1608 10613.65,9262.78 r180 top
C52 "220nF 10V" CAPC1608 10597.9,8613.17 r0 bottom
C53 "10nF 16V" CAPC1005 10609.71,8621.04 r0 top
C54 "10nF 16V" CAPC1005 10613.65,9219.47 r180 top
C55 "220nF 10V" CAPC1608 10629.4,6542.3 r0 bottom
C56 "220nF 10V" CAPC1608 10597.9,7077.74 r180 bottom
C57 "10nF 16V" CAPC1005 10609.71,7073.8 r180 top
C58 "10nF 16V" CAPC1005 10613.65,6471.44 r0 top
C59 "0.1uF 16V" CAPC1005 11755.38,7896.63 r0 bottom
C60 "0.1uF 16V" CAPC1005 11755.38,7857.26 r0 bottom
C61 "10nF 16V" CAPC1005 12023.1,7873.01 r0 bottom
C62 "0.1uF 16V" CAPC1005 11507.35,9349.39 r90 bottom
C63 "0.1uF 16V" CAPC1005 12023.1,7817.89 r0 bottom
C64 "10uF 16V" CAPC3528 11755.38,8061.99 r90 bottom
C65 "10uF 16V" CAPC3528 11605.78,8061.99 r90 bottom
C66 "10uF 16V" CAPC3528 11755.38,8337.58 r90 bottom
C67 "10uF 16V" CAPC3528 11302.63,8337.58 r270 bottom
C68 "0.1uF 16V" CAPC1005 11015.22,8353.33 r270 top
C69 "0.1uF 16V" CAPC1005 11298.69,7817.89 r0 bottom
C70 "0.1uF 16V" CAPC1005 11015.22,8038.37 r270 top
C71 "0.1uF 16V" CAPC1005 10999.48,8195.85 r270 top
C72 "0.1uF 16V" CAPC1005 11779,7817.89 r180 bottom
C73 "0.1uF 16V" CAPC1005 11534.91,7817.89 r0 bottom
C74 "0.1uF 16V" CAPC1005 12023.1,8038.37 r90 bottom
C75 "0.1uF 16V" CAPC1005 12023.1,8376.95 r270 top
C76 "0.1uF 16V" CAPC1005 11660.89,8676.16 r180 top
C77 "0.1uF 16V" CAPC1005 11369.56,8546.24 r180 bottom
C78 "10nF 16V" CAPC1005 11054.59,8353.33 r270 top
C79 "10nF 16V" CAPC1005 11298.69,7778.52 r0 bottom
C80 "10nF 16V" CAPC1005 11054.59,8038.37 r270 top
C81 "10nF 16V" CAPC1005 11038.85,8195.85 r270 top
C82 "10nF 16V" CAPC1005 11779,7778.52 r180 bottom
C83 "10nF 16V" CAPC1005 11534.91,7778.52 r0 bottom
C84 "10nF 16V" CAPC1005 12023.1,8054.11 r90 top
C85 "10nF 16V" CAPC1005 12023.1,8416.32 r90 bottom
C86 "10nF 16V" CAPC1005 11660.89,8636.79 r180 top
C87 "10nF 16V" CAPC1005 11369.56,8514.74 r180 bottom
C88 "10uF 16V" CAPC3528 11302.63,8061.99 r90 bottom
C89 "10uF 16V" CAPC3528 11605.78,8337.58 r90 bottom
C90 "0.1uF 16V" CAPC1005 11845.93,7939.94 r180 bottom
C91 "0.1uF 16V" CAPC1005 11680.58,7845.45 r90 bottom
C92 "0.1uF 16V" CAPC1005 11180.58,7829.7 r270 bottom
C93 "0.1uF 16V" CAPC1005 12038.85,8258.84 r90 top
C94 "0.1uF 16V" CAPC1005 11826.25,8699.78 r180 top
C95 "0.1uF 16V" CAPC1005 11503.41,8699.78 r180 top
C96 "10nF 16V" CAPC1005 11503.41,8660.41 r180 top
C97 "10nF 16V" CAPC1005 11141.21,7829.7 r270 bottom
C98 "10nF 16V" CAPC1005 11641.21,7845.45 r90 bottom
C99 "10nF 16V" CAPC1005 11845.93,7900.57 r180 bottom
C100 "10nF 16V" CAPC1005 11826.25,8660.41 r180 top
C101 "10nF 16V" CAPC1005 11999.48,8258.84 r90 top
C102 "10uF 16V" CAPC3528 11097.9,7522.62 r90 top
C103 "0.1uF 16V" CAPC1005 10928.61,7424.19 r0 top
C104 "10nF 16V" CAPC1005 10759.32,7455.69 r270 top
C105 "10nF 16V" CAPC1005 10719.95,7455.69 r270 top
C106 "10nF 16V" CAPC1005 10928.61,7463.56 r0 top
C107 "10nF 16V" CAPC1005 11806.56,7376.95 r180 top
C108 "10nF 16V" CAPC1005 11538.85,7191.91 r270 top
C109 "10nF 16V" CAPC1005 11389.24,7376.95 r180 top
C110 "10uF 16V" CAPC3528 11349.87,7128.92 r180 top
C111 "10uF 16V" CAPC3528 11779,7124.98 r0 top
C112 "0.1uF 16V" CAPC1005 11806.56,7298.21 r180 top
C113 "0.1uF 16V" CAPC1005 11964.04,7467.5 r270 top
C114 "10nF 16V" CAPC1005 11931.56,7181.1 r270 top
C115 "10nF 16V" CAPC1005 11806.56,7258.84 r0 top
C116 "10nF 16V" CAPC1005 11806.56,7337.58 r0 top
C117 "10nF 16V" CAPC1005 11806.56,7219.47 r180 top
C118 "0.1uF 16V" CAPC1005 11389.24,7298.21 r180 top
C119 "10nF 16V" CAPC1005 11389.24,7258.84 r0 top
C120 "10nF 16V" CAPC1005 11389.24,7219.47 r180 top
C121 "10nF 16V" CAPC1005 11389.24,7337.58 r0 top
C122 "0.1uF 16V" CAPC1005 11530.97,7569.86 r90 top
C123 "10uF 16V" CAPC3528 11542.78,8845.45 r90 top
C124 "220nF 10V" CAPC1608 10897.11,9235.22 r180 top
C125 "10uF 16V" CAPC3528 11586.09,6849.39 r90 top
C126 "220uF 4V" CAPC7343 11956.17,6841.52 r270 top
C127 "220uF 4V" CAPC7343 9779,9164.35 r90 top
C128 "220uF 4V" CAPC7343 9471.92,8191.91 r90 bottom
C129 "220uF 4V" CAPC7343 10782.94,8152.54 r0 bottom
C130 "220uF 4V" CAPC7343 9530.97,9164.35 r90 top
C131 "220uF 4V" CAPC7343 10133.33,9282.46 r180 top
C132 "220uF 4V" CAPC7343 11404.99,6849.39 r90 top
C133 "220uF 4V" CAPC7343 11956.17,8869.07 r90 top
D1 "200mA 30V" SOT95P230-3 11460.11,8101.36 r90 bottom
HDR1 "DOCKSTAT M HEADER" 54075 10719.95,8845.45 r0 bottom locked
HDR2 "DOCKSTAT M HEADER" 54075 10719.95,6845.45 r0 bottom locked
LED1 "RED" LED2013 11310.5,6546.24 r180 top locked
LED2 "GREEN" LED2013 10129.4,6546.24 r180 top locked
LED3 "RED" LED2013 11889.24,9589.55 r180 top
P1 "1x2 HEADER" HDR1X2 10487.67,9955.69 r270 top
P2 "2x10 IDC HEADER" IDC2.54-V20D 11353.81,9904.51 r180 top locked
P3_ch1 "Header 6" HDR1X6 10030.76,5443.08 r180 top (schematic designator P3)
P3_ch2 "Header 6" HDR1X6 10030.76,5701.87 r180 top (schematic designator P3)
P3_ch3 "Header 6" HDR1X6 10034.7,5944.92 r180 top (schematic designator P3)
P3_ch4 "Header 6" HDR1X6 10032.73,6194.86 r180 top (schematic designator P3)
P4_ch1 "Header 6" HDR1X6 11953.62,5402.74 r180 top (schematic designator P4)
P4_ch2 "Header 6" HDR1X6 11953.62,5661.53 r180 top (schematic designator P4)
P4_ch3 "Header 6" HDR1X6 11957.56,5904.58 r180 top (schematic designator P4)
P4_ch4 "Header 6" HDR1X6 11955.59,6154.51 r180 top (schematic designator P4)
P5 "Header 3" HDR1X3 10630.02,9942.91 r270 top
R1 "4K7 5%" RESC1005 11586.09,9128.92 r270 bottom
R2 "100R 5%" RESC2012 10511.29,8542.3 r0 top
R3 "100R 5%" RESC2012 10904.99,9128.92 r90 bottom
R4 "100R 5%" RESC2012 10999.48,9128.92 r90 bottom
R5 "270R 1%" RESC2012 11546.72,6546.24 r180 top
R6 "100R 5%" RESC2012 11204.2,8845.45 r90 top
R7 "100R 5%" RESC2012 10499.48,9176.16 r180 bottom
R8 "100R 5%" RESC2012 9428.61,8581.67 r270 top
R9 "100R 5%" RESC2012 9452.23,8250.96 r270 top
R10 "100R 5%" RESC2012 9507.35,8581.67 r270 top
R11 "100R 5%" RESC2012 11082.15,9128.92 r90 bottom
R12 "100R 5%" RESC2012 11125.46,8845.45 r270 top
R13 "100R 5%" RESC2012 11046.72,8845.45 r270 top
R14 "100R 5%" RESC2012 11251.45,9128.92 r270 bottom
R15 "4K7 5%" RESC1005 11046.72,9121.04 r180 top
R16 "100R 5%" RESC2012 9861.68,6601.36 r180 top
R17 "4K7 5%" RESC1005 10479.79,9223.41 r0 top
R18 "4K7 5%" RESC1005 11046.72,9073.8 r180 top
R19 "4K7 5%" RESC1005 10334.12,6487.18 r0 top
R20 "4K7 5%" RESC1005 11601.84,7845.45 r270 bottom
R21 "4K7 5%" RESC1005 11944.36,8085.61 r180 bottom
R22 "4K7 5%" RESC1005 11944.36,8046.24 r180 bottom
R23 "4K7 5%" RESC1005 11944.36,8006.87 r180 bottom
R24 "4K7 5%" RESC1005 11046.72,9168.29 r0 top
R25 "4K7 5%" RESC1005 11944.36,8439.94 r180 bottom
R26 "4K7 5%" RESC1005 11944.36,8400.57 r180 bottom
R27 "4K7 5%" RESC1005 11944.36,8361.2 r180 bottom
R28 "4K7 5%" RESC1005 11944.36,8321.83 r180 bottom
R29 "4K7 5%" RESC1005 11605.78,8199.78 r0 bottom
R30 "4K7 5%" RESC1005 11755.38,8199.78 r0 bottom
R31 "4K7 5%" RESC1005 11944.36,8282.46 r180 bottom
R32 "4K7 5%" RESC1005 11944.36,8243.09 r180 bottom
R33 "4K7 5%" RESC1005 11944.36,8164.35 r180 bottom
R34 "4K7 5%" RESC1005 11944.36,8124.98 r180 bottom
R35 "4K7 5%" RESC1005 11944.36,8203.72 r180 bottom
R36 "4K7 5%" RESC1005 11330.19,7920.26 r0 bottom
R37 "270R 1%" RESC2012 11456.17,7979.31 r180 bottom
R38 "10M 5%" RESC2012 12027.04,7939.94 r90 top
R39 "4K7 5%" RESC1005 11944.36,8479.31 r180 bottom
R40 "4K7 5%" RESC1005 11944.36,8558.05 r0 bottom
R41 "4K7 5%" RESC1005 11873.49,8581.67 r270 bottom
R42 "4K7 5%" RESC1005 11834.12,8581.67 r270 bottom
R43 "4K7 5%" RESC1005 11794.75,8581.67 r270 bottom
R44 "4K7 5%" RESC1005 11330.19,7873.01 r0 bottom
R45 "4K7 5%" RESC1005 11755.38,8581.67 r270 bottom
R46 "270R 1%" RESC2012 11456.17,7888.76 r180 bottom
R47 "10M 5%" RESC2012 12027.04,7739.15 r90 top
R48 "4K7 5%" RESC1005 11944.36,8518.68 r180 bottom
R49 "4K7 5%" RESC1005 11944.36,8597.42 r0 bottom
R50 "4K7 5%" RESC1005 11676.64,8581.67 r270 bottom
R51 "4K7 5%" RESC1005 11716.01,8581.67 r270 bottom
R52 "4K7 5%" RESC1005 11597.9,8581.67 r270 bottom
R53 "4K7 5%" RESC1005 11637.27,8581.67 r270 bottom
R54 "4K7 5%" RESC1005 11515.22,8581.67 r270 bottom
R55 "4K7 5%" RESC1005 11475.85,8581.67 r270 bottom
R56 "4K7 5%" RESC1005 11436.48,8581.67 r90 bottom
R57 "4K7 5%" RESC1005 11467.98,9128.92 r270 bottom
R58 "270R 1%" RESC2012 11267.19,9341.52 r0 top
R59 "100R 5%" RESC2012 11460.11,8227.34 r0 bottom
R60 "4K7 5%" RESC1005 11507.35,9128.92 r90 bottom
R61 "4K7 5%" RESC1005 11637.27,9128.92 r270 bottom
R62 "4K7 5%" RESC1005 11586.09,9349.39 r90 bottom
R63 "4K7 5%" RESC1005 11660.89,9349.39 r270 bottom
R64 "270R 1%" RESC2012 11097.9,6530.49 r0 top
R65 "270R 1%" RESC2012 11097.9,6451.75 r180 top
R66 "4K7 5%" RESC1005 11460.11,9349.39 r270 bottom
R67 "4K7 5%" RESC1005 11412.86,9349.39 r270 bottom
R68_ch1 "50R 1%" RESC2012 11601.35,5501.14 r0 top (schematic designator R68)
R68_ch2 "50R 1%" RESC2012 11601.35,5759.93 r0 top (schematic designator R68)
R68_ch3 "50R 1%" RESC2012 11605.29,6002.98 r0 top (schematic designator R68)
R68_ch4 "50R 1%" RESC2012 11603.32,6252.91 r0 top (schematic designator R68)
R69_ch1 "50R 1%" RESC2012 11902.33,5502.12 r0 top (schematic designator R69)
R69_ch2 "50R 1%" RESC2012 11902.33,5760.91 r0 top (schematic designator R69)
R69_ch3 "50R 1%" RESC2012 11906.26,6003.96 r0 top (schematic designator R69)
R69_ch4 "50R 1%" RESC2012 11904.3,6253.9 r0 top (schematic designator R69)
R70_ch1 "50R 1%" RESC2012 9983.53,5341.73 r0 top (schematic designator R70)
R70_ch2 "50R 1%" RESC2012 9983.53,5600.52 r0 top (schematic designator R70)
R70_ch3 "50R 1%" RESC2012 9987.46,5843.57 r0 top (schematic designator R70)
R70_ch4 "50R 1%" RESC2012 9985.5,6093.5 r0 top (schematic designator R70)
R71_ch1 "50R 1%" RESC2012 9680.46,5340.74 r0 top (schematic designator R71)
R71_ch2 "50R 1%" RESC2012 9680.46,5599.54 r0 top (schematic designator R71)
R71_ch3 "50R 1%" RESC2012 9684.39,5842.58 r0 top (schematic designator R71)
R71_ch4 "50R 1%" RESC2012 9682.42,6092.52 r0 top (schematic designator R71)
TP1 "3V3" TestPin 9412.86,9569.86 r0 top
TP2 "1V8" TestPin 9412.86,9711.59 r90 top
TP3 "PROC_TDO" TestPin 11322.31,9621.04 r90 top
TP4 "PROC_TCK" TestPin 11676.64,9621.04 r90 top
TP5 "PROC_TMS" TestPin 11440.42,9621.04 r90 top
TP6 "PROC_TDI" TestPin 11558.53,9621.04 r90 top
TP7 "2V5" TestPin 9412.86,9640.73 r90 top
TP8 "5V0" TestPin 9412.86,9499 r90 top
TP9 "1V25" TestPin 9412.84,9782.45 r90 top
TP10 "GND" TestPin 9412.86,9853.33 r90 top
U1 "XC3S1000-4FG456C" BGA100P22X22-456 10097.9,7750.96 r0 top locked
U2 "SN74LVC1G04DBV" SOT95P280-5 9483.73,6534.43 r0 top
U3 "SRAM-256Kx16" TSOP80P1176-44 10613.65,8920.26 r0 top locked
U4 "SRAM-256Kx16" TSOP80P1176-44 10613.65,6770.65 r0 top locked
U5 "LH79520N0M000" QFP40P2000X2000-176 11527.04,8164.35 r0 top locked
U6 "74LCX157" TSOP65P638-16 11597.9,9239.15 r0 top locked
U7 "SDRAM-16Mx16" BGA80P9X6-54 11389.24,7376.95 r270 bottom locked
U8 "FLASH-4Mx16" BGA80P12X8-63 10881.37,7550.18 r90 bottom locked
U9 "SDRAM-16Mx16" BGA80P9X6-54 11806.56,7376.95 r270 bottom locked
U10 "VRG-100mA-1.2V-37V-4%-75102" SOP127P600-8 11093.96,6471.44 r270 bottom locked
U11 "LM1084IS-ADJ" TO254P1435-4 10971.92,9569.86 r270 bottom

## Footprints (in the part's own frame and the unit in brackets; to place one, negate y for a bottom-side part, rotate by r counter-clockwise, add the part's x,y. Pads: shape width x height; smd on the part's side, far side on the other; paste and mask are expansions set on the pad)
54075 [mm] "Connector; Docking Station, Receptacle; 100 Position; Vertical"
  rect 0.5x1.9 smd: 1(-19.6,3.4) 2(-19.6,-3.4) 3(-18.8,3.4) 4(-18.8,-3.4) 5(-18,3.4) 6(-18,-3.4) 7(-17.2,3.4) 8(-17.2,-3.4) 9(-16.4,3.4) 10(-16.4,-3.4) 11(-15.6,3.4) 12(-15.6,-3.4) 13(-14.8,3.4) 14(-14.8,-3.4) 15(-14,3.4) 16(-14,-3.4) 17(-13.2,3.4) 18(-13.2,-3.4) 19(-12.4,3.4) 20(-12.4,-3.4) 21(-11.6,3.4) 22(-11.6,-3.4) 23(-10.8,3.4) 24(-10.8,-3.4) 25(-10,3.4) 26(-10,-3.4) 27(-9.2,3.4) 28(-9.2,-3.4) 29(-8.4,3.4) 30(-8.4,-3.4) 31(-7.6,3.4) 32(-7.6,-3.4) 33(-6.8,3.4) 34(-6.8,-3.4) 35(-6,3.4) 36(-6,-3.4) 37(-5.2,3.4) 38(-5.2,-3.4) 39(-4.4,3.4) 40(-4.4,-3.4) 41(-3.6,3.4) 42(-3.6,-3.4) 43(-2.8,3.4) 44(-2.8,-3.4) 45(-2,3.4) 46(-2,-3.4) 47(-1.2,3.4) 48(-1.2,-3.4) 49(-0.4,3.4) 50(-0.4,-3.4) 51(0.4,3.4) 52(0.4,-3.4) 53(1.2,3.4) 54(1.2,-3.4) 55(2,3.4) 56(2,-3.4) 57(2.8,3.4) 58(2.8,-3.4) 59(3.6,3.4) 60(3.6,-3.4) 61(4.4,3.4) 62(4.4,-3.4) 63(5.2,3.4) 64(5.2,-3.4) 65(6,3.4) 66(6,-3.4) 67(6.8,3.4) 68(6.8,-3.4) 69(7.6,3.4) 70(7.6,-3.4) 71(8.4,3.4) 72(8.4,-3.4) 73(9.2,3.4) 74(9.2,-3.4) 75(10,3.4) 76(10,-3.4) 77(10.8,3.4) 78(10.8,-3.4) 79(11.6,3.4) 80(11.6,-3.4) 81(12.4,3.4) 82(12.4,-3.4) 83(13.2,3.4) 84(13.2,-3.4) 85(14,3.4) 86(14,-3.4) 87(14.8,3.4) 88(14.8,-3.4) 89(15.6,3.4) 90(15.6,-3.4) 91(16.4,3.4) 92(16.4,-3.4) 93(17.2,3.4) 94(17.2,-3.4) 95(18,3.4) 96(18,-3.4) 97(18.8,3.4) 98(18.8,-3.4) 99(19.6,3.4) 100(19.6,-3.4)
  round 0.5 hole 0.7 unplated mask+0.1: MH1(-26.7,4.2) MH2(-25.9,-4.2) MH3(26.7,4.2) MH4(25.9,-4.2)
  round 4.8 hole 5.1 unplated mask+0.1: MH5(-26.3,0) MH6(26.3,0)
  Top Layer keep-out region: -20.15,2.15 20.15,2.15 20.15,-2.15 -20.15,-2.15
  silkscreen extent -30.35,-4.4 30.35,5.02
BGA80P9X6-54 [mm] "BGA; 54 Balls; Body 8 x 14 mm; Pitch 0.8 mm (FG Package)"
  round 0.35 smd: A1(3.2,3.2) A2(3.2,2.4) A3(3.2,1.6) A7(3.2,-1.6) A8(3.2,-2.4) A9(3.2,-3.2) B1(2.4,3.2) B2(2.4,2.4) B3(2.4,1.6) B7(2.4,-1.6) B8(2.4,-2.4) B9(2.4,-3.2) C1(1.6,3.2) C2(1.6,2.4) C3(1.6,1.6) C7(1.6,-1.6) C8(1.6,-2.4) C9(1.6,-3.2) D1(0.8,3.2) D2(0.8,2.4) D3(0.8,1.6) D7(0.8,-1.6) D8(0.8,-2.4) D9(0.8,-3.2) E1(0,3.2) E2(0,2.4) E3(0,1.6) E7(0,-1.6) E8(0,-2.4) E9(0,-3.2) F1(-0.8,3.2) F2(-0.8,2.4) F3(-0.8,1.6) F7(-0.8,-1.6) F8(-0.8,-2.4) F9(-0.8,-3.2) G1(-1.6,3.2) G2(-1.6,2.4) G3(-1.6,1.6) G7(-1.6,-1.6) G8(-1.6,-2.4) G9(-1.6,-3.2) H1(-2.4,3.2) H2(-2.4,2.4) H3(-2.4,1.6) H7(-2.4,-1.6) H8(-2.4,-2.4) H9(-2.4,-3.2) J1(-3.2,3.2) J2(-3.2,2.4) J3(-3.2,1.6) J7(-3.2,-1.6) J8(-3.2,-2.4) J9(-3.2,-3.2)
  silkscreen extent -7,-4 7,4.78
BGA80P12X8-63 [mm] "BGA; 63 Balls; Body 12 x 11 mm; Pitch 0.8 mm"
  round 0.3 smd: A1(4.4,2.8) A2(4.4,2) A7(4.4,-2) A8(4.4,-2.8) B1(3.6,2.8) B7(3.6,-2) B8(3.6,-2.8) C2(2.8,2) C3(2.8,1.2) C4(2.8,0.4) C5(2.8,-0.4) C6(2.8,-1.2) C7(2.8,-2) D2(2,2) D3(2,1.2) D4(2,0.4) D5(2,-0.4) D6(2,-1.2) D7(2,-2) E2(1.2,2) E3(1.2,1.2) E4(1.2,0.4) E5(1.2,-0.4) E6(1.2,-1.2) E7(1.2,-2) F2(0.4,2) F3(0.4,1.2) F4(0.4,0.4) F5(0.4,-0.4) F6(0.4,-1.2) F7(0.4,-2) G2(-0.4,2) G3(-0.4,1.2) G4(-0.4,0.4) G5(-0.4,-0.4) G6(-0.4,-1.2) G7(-0.4,-2) H2(-1.2,2) H3(-1.2,1.2) H4(-1.2,0.4) H5(-1.2,-0.4) H6(-1.2,-1.2) H7(-1.2,-2) J2(-2,2) J3(-2,1.2) J4(-2,0.4) J5(-2,-0.4) J6(-2,-1.2) J7(-2,-2) K2(-2.8,2) K3(-2.8,1.2) K4(-2.8,0.4) K5(-2.8,-0.4) K6(-2.8,-1.2) K7(-2.8,-2) L1(-3.6,2.8) L2(-3.6,2) L7(-3.6,-2) L8(-3.6,-2.8) M1(-4.4,2.8) M2(-4.4,2) M7(-4.4,-2) M8(-4.4,-2.8)
  silkscreen extent -6,-5.5 6,6.28
BGA100P22X22-456 [mm] "456-Ball Fine-Pitch Ball Grid Array (FG456)"
  round 0.5 smd: A1(-10.5,10.5) A2(-9.5,10.5) A3(-8.5,10.5) A4(-7.5,10.5) A5(-6.5,10.5) A6(-5.5,10.5) A7(-4.5,10.5) A8(-3.5,10.5) A9(-2.5,10.5) A10(-1.5,10.5) A11(-0.5,10.5) A12(0.5,10.5) A13(1.5,10.5) A14(2.5,10.5) A15(3.5,10.5) A16(4.5,10.5) A17(5.5,10.5) A18(6.5,10.5) A19(7.5,10.5) A20(8.5,10.5) A21(9.5,10.5) A22(10.5,10.5) AA1(-10.5,-9.5) AA2(-9.5,-9.5) AA3(-8.5,-9.5) AA4(-7.5,-9.5) AA5(-6.5,-9.5) AA6(-5.5,-9.5) AA7(-4.5,-9.5) AA8(-3.5,-9.5) AA9(-2.5,-9.5) AA10(-1.5,-9.5) AA11(-0.5,-9.5) AA12(0.5,-9.5) AA13(1.5,-9.5) AA14(2.5,-9.5) AA15(3.5,-9.5) AA16(4.5,-9.5) AA17(5.5,-9.5) AA18(6.5,-9.5) AA19(7.5,-9.5) AA20(8.5,-9.5) AA21(9.5,-9.5) AA22(10.5,-9.5) AB1(-10.5,-10.5) AB2(-9.5,-10.5) AB3(-8.5,-10.5) AB4(-7.5,-10.5) AB5(-6.5,-10.5) AB6(-5.5,-10.5) AB7(-4.5,-10.5) AB8(-3.5,-10.5) AB9(-2.5,-10.5) AB10(-1.5,-10.5) AB11(-0.5,-10.5) AB12(0.5,-10.5) AB13(1.5,-10.5) AB14(2.5,-10.5) AB15(3.5,-10.5) AB16(4.5,-10.5) AB17(5.5,-10.5) AB18(6.5,-10.5) AB19(7.5,-10.5) AB20(8.5,-10.5) AB21(9.5,-10.5) AB22(10.5,-10.5) B1(-10.5,9.5) B2(-9.5,9.5) B3(-8.5,9.5) B4(-7.5,9.5) B5(-6.5,9.5) B6(-5.5,9.5) B7(-4.5,9.5) B8(-3.5,9.5) B9(-2.5,9.5) B10(-1.5,9.5) B11(-0.5,9.5) B12(0.5,9.5) B13(1.5,9.5) B14(2.5,9.5) B15(3.5,9.5) B16(4.5,9.5) B17(5.5,9.5) B18(6.5,9.5) B19(7.5,9.5) B20(8.5,9.5) B21(9.5,9.5) B22(10.5,9.5) C1(-10.5,8.5) C2(-9.5,8.5) C3(-8.5,8.5) C4(-7.5,8.5) C5(-6.5,8.5) C6(-5.5,8.5) C7(-4.5,8.5) C8(-3.5,8.5) C9(-2.5,8.5) C10(-1.5,8.5) C11(-0.5,8.5) C12(0.5,8.5) C13(1.5,8.5) C14(2.5,8.5) C15(3.5,8.5) C16(4.5,8.5) C17(5.5,8.5) C18(6.5,8.5) C19(7.5,8.5) C20(8.5,8.5) C21(9.5,8.5) C22(10.5,8.5) D1(-10.5,7.5) D2(-9.5,7.5) D3(-8.5,7.5) D4(-7.5,7.5) D5(-6.5,7.5) D6(-5.5,7.5) D7(-4.5,7.5) D8(-3.5,7.5) D9(-2.5,7.5) D10(-1.5,7.5) D11(-0.5,7.5) D12(0.5,7.5) D13(1.5,7.5) D14(2.5,7.5) D15(3.5,7.5) D16(4.5,7.5) D17(5.5,7.5) D18(6.5,7.5) D19(7.5,7.5) D20(8.5,7.5) D21(9.5,7.5) D22(10.5,7.5) E1(-10.5,6.5) E2(-9.5,6.5) E3(-8.5,6.5) E4(-7.5,6.5) E5(-6.5,6.5) E6(-5.5,6.5) E7(-4.5,6.5) E8(-3.5,6.5) E9(-2.5,6.5) E10(-1.5,6.5) E11(-0.5,6.5) E12(0.5,6.5) E13(1.5,6.5) E14(2.5,6.5) E15(3.5,6.5) E16(4.5,6.5) E17(5.5,6.5) E18(6.5,6.5) E19(7.5,6.5) E20(8.5,6.5) E21(9.5,6.5) E22(10.5,6.5) F1(-10.5,5.5) F2(-9.5,5.5) F3(-8.5,5.5) F4(-7.5,5.5) F5(-6.5,5.5) F6(-5.5,5.5) F7(-4.5,5.5) F8(-3.5,5.5) F9(-2.5,5.5) F10(-1.5,5.5) F11(-0.5,5.5) F12(0.5,5.5) F13(1.5,5.5) F14(2.5,5.5) F15(3.5,5.5) F16(4.5,5.5) F17(5.5,5.5) F18(6.5,5.5) F19(7.5,5.5) F20(8.5,5.5) F21(9.5,5.5) F22(10.5,5.5) G1(-10.5,4.5) G2(-9.5,4.5) G3(-8.5,4.5) G4(-7.5,4.5) G5(-6.5,4.5) G6(-5.5,4.5) G7(-4.5,4.5) G8(-3.5,4.5) G9(-2.5,4.5) G10(-1.5,4.5) G11(-0.5,4.5) G12(0.5,4.5) G13(1.5,4.5) G14(2.5,4.5) G15(3.5,4.5) G16(4.5,4.5) G17(5.5,4.5) G18(6.5,4.5) G19(7.5,4.5) G20(8.5,4.5) G21(9.5,4.5) G22(10.5,4.5) H1(-10.5,3.5) H2(-9.5,3.5) H3(-8.5,3.5) H4(-7.5,3.5) H5(-6.5,3.5) H6(-5.5,3.5) H7(-4.5,3.5) H16(4.5,3.5) H17(5.5,3.5) H18(6.5,3.5) H19(7.5,3.5) H20(8.5,3.5) H21(9.5,3.5) H22(10.5,3.5) J1(-10.5,2.5) J2(-9.5,2.5) J3(-8.5,2.5) J4(-7.5,2.5) J5(-6.5,2.5) J6(-5.5,2.5) J7(-4.5,2.5) J9(-2.5,2.5) J10(-1.5,2.5) J11(-0.5,2.5) J12(0.5,2.5) J13(1.5,2.5) J14(2.5,2.5) J16(4.5,2.5) J17(5.5,2.5) J18(6.5,2.5) J19(7.5,2.5) J20(8.5,2.5) J21(9.5,2.5) J22(10.5,2.5) K1(-10.5,1.5) K2(-9.5,1.5) K3(-8.5,1.5) K4(-7.5,1.5) K5(-6.5,1.5) K6(-5.5,1.5) K7(-4.5,1.5) K9(-2.5,1.5) K10(-1.5,1.5) K11(-0.5,1.5) K12(0.5,1.5) K13(1.5,1.5) K14(2.5,1.5) K16(4.5,1.5) K17(5.5,1.5) K18(6.5,1.5) K19(7.5,1.5) K20(8.5,1.5) K21(9.5,1.5) K22(10.5,1.5) L1(-10.5,0.5) L2(-9.5,0.5) L3(-8.5,0.5) L4(-7.5,0.5) L5(-6.5,0.5) L6(-5.5,0.5) L7(-4.5,0.5) L9(-2.5,0.5) L10(-1.5,0.5) L11(-0.5,0.5) L12(0.5,0.5) L13(1.5,0.5) L14(2.5,0.5) L16(4.5,0.5) L17(5.5,0.5) L18(6.5,0.5) L19(7.5,0.5) L20(8.5,0.5) L21(9.5,0.5) L22(10.5,0.5) M1(-10.5,-0.5) M2(-9.5,-0.5) M3(-8.5,-0.5) M4(-7.5,-0.5) M5(-6.5,-0.5) M6(-5.5,-0.5) M7(-4.5,-0.5) M9(-2.5,-0.5) M10(-1.5,-0.5) M11(-0.5,-0.5) M12(0.5,-0.5) M13(1.5,-0.5) M14(2.5,-0.5) M16(4.5,-0.5) M17(5.5,-0.5) M18(6.5,-0.5) M19(7.5,-0.5) M20(8.5,-0.5) M21(9.5,-0.5) M22(10.5,-0.5) N1(-10.5,-1.5) N2(-9.5,-1.5) N3(-8.5,-1.5) N4(-7.5,-1.5) N5(-6.5,-1.5) N6(-5.5,-1.5) N7(-4.5,-1.5) N9(-2.5,-1.5) N10(-1.5,-1.5) N11(-0.5,-1.5) N12(0.5,-1.5) N13(1.5,-1.5) N14(2.5,-1.5) N16(4.5,-1.5) N17(5.5,-1.5) N18(6.5,-1.5) N19(7.5,-1.5) N20(8.5,-1.5) N21(9.5,-1.5) N22(10.5,-1.5) P1(-10.5,-2.5) P2(-9.5,-2.5) P3(-8.5,-2.5) P4(-7.5,-2.5) P5(-6.5,-2.5) P6(-5.5,-2.5) P7(-4.5,-2.5) P9(-2.5,-2.5) P10(-1.5,-2.5) P11(-0.5,-2.5) P12(0.5,-2.5) P13(1.5,-2.5) P14(2.5,-2.5) P16(4.5,-2.5) P17(5.5,-2.5) P18(6.5,-2.5) P19(7.5,-2.5) P20(8.5,-2.5) P21(9.5,-2.5) P22(10.5,-2.5) R1(-10.5,-3.5) R2(-9.5,-3.5) R3(-8.5,-3.5) R4(-7.5,-3.5) R5(-6.5,-3.5) R6(-5.5,-3.5) R7(-4.5,-3.5) R16(4.5,-3.5) R17(5.5,-3.5) R18(6.5,-3.5) R19(7.5,-3.5) R20(8.5,-3.5) R21(9.5,-3.5) R22(10.5,-3.5) T1(-10.5,-4.5) T2(-9.5,-4.5) T3(-8.5,-4.5) T4(-7.5,-4.5) T5(-6.5,-4.5) T6(-5.5,-4.5) T7(-4.5,-4.5) T8(-3.5,-4.5) T9(-2.5,-4.5) T10(-1.5,-4.5) T11(-0.5,-4.5) T12(0.5,-4.5) T13(1.5,-4.5) T14(2.5,-4.5) T15(3.5,-4.5) T16(4.5,-4.5) T17(5.5,-4.5) T18(6.5,-4.5) T19(7.5,-4.5) T20(8.5,-4.5) T21(9.5,-4.5) T22(10.5,-4.5) U1(-10.5,-5.5) U2(-9.5,-5.5) U3(-8.5,-5.5) U4(-7.5,-5.5) U5(-6.5,-5.5) U6(-5.5,-5.5) U7(-4.5,-5.5) U8(-3.5,-5.5) U9(-2.5,-5.5) U10(-1.5,-5.5) U11(-0.5,-5.5) U12(0.5,-5.5) U13(1.5,-5.5) U14(2.5,-5.5) U15(3.5,-5.5) U16(4.5,-5.5) U17(5.5,-5.5) U18(6.5,-5.5) U19(7.5,-5.5) U20(8.5,-5.5) U21(9.5,-5.5) U22(10.5,-5.5) V1(-10.5,-6.5) V2(-9.5,-6.5) V3(-8.5,-6.5) V4(-7.5,-6.5) V5(-6.5,-6.5) V6(-5.5,-6.5) V7(-4.5,-6.5) V8(-3.5,-6.5) V9(-2.5,-6.5) V10(-1.5,-6.5) V11(-0.5,-6.5) V12(0.5,-6.5) V13(1.5,-6.5) V14(2.5,-6.5) V15(3.5,-6.5) V16(4.5,-6.5) V17(5.5,-6.5) V18(6.5,-6.5) V19(7.5,-6.5) V20(8.5,-6.5) V21(9.5,-6.5) V22(10.5,-6.5) W1(-10.5,-7.5) W2(-9.5,-7.5) W3(-8.5,-7.5) W4(-7.5,-7.5) W5(-6.5,-7.5) W6(-5.5,-7.5) W7(-4.5,-7.5) W8(-3.5,-7.5) W9(-2.5,-7.5) W10(-1.5,-7.5) W11(-0.5,-7.5) W12(0.5,-7.5) W13(1.5,-7.5) W14(2.5,-7.5) W15(3.5,-7.5) W16(4.5,-7.5) W17(5.5,-7.5) W18(6.5,-7.5) W19(7.5,-7.5) W20(8.5,-7.5) W21(9.5,-7.5) W22(10.5,-7.5) Y1(-10.5,-8.5) Y2(-9.5,-8.5) Y3(-8.5,-8.5) Y4(-7.5,-8.5) Y5(-6.5,-8.5) Y6(-5.5,-8.5) Y7(-4.5,-8.5) Y8(-3.5,-8.5) Y9(-2.5,-8.5) Y10(-1.5,-8.5) Y11(-0.5,-8.5) Y12(0.5,-8.5) Y13(1.5,-8.5) Y14(2.5,-8.5) Y15(3.5,-8.5) Y16(4.5,-8.5) Y17(5.5,-8.5) Y18(6.5,-8.5) Y19(7.5,-8.5) Y20(8.5,-8.5) Y21(9.5,-8.5) Y22(10.5,-8.5)
  silkscreen extent -12.27,-11.5 11.5,11.5
CAPC1005 [mm]
  rect 0.6x0.5 smd: 1(-0.5,0) 2(0.5,0)
  silkscreen extent -0.1,-0.2 0.1,0.2
CAPC1608 [mm]
  rect 1.1x1 smd: 1(-0.85,0) 2(0.85,0)
  silkscreen extent -1.7,-0.4 -1.7,0.4
CAPC3528 [mm]
  rect 2x2.2 smd: 1(-1.5,0) 2(1.5,0)
  silkscreen extent -2.3,-1.6 1.8,1.6
CAPC7343 [mm]
  rect 2.6x2.4 smd: 1(-3.202,0.007) 2(3.198,0.007)
  silkscreen extent -4.2,-2.39 3.7,2.41
HDR1X2 [mm] "Connector; Header; 2 Position"
  rect 1.5x1.5 hole 0.889: 1(0,0)
  round 1.5 hole 0.889: 2(2.54,0)
  silkscreen extent -1.27,-1.27 3.81,1.27
HDR1X3 [mm] "Connector; Header; 3 Position"
  rect 1.5x1.5 hole 0.9: 1(0,0)
  round 1.5 hole 0.9: 2(2.54,0) 3(5.08,0)
  silkscreen extent -1.27,-1.27 6.35,1.27
HDR1X6 [mm] "Connector; Header; 6 Position"
  rect 1.5x1.5 hole 0.9: 1(0,0)
  round 1.5 hole 0.9: 2(2.54,0) 3(5.08,0) 4(7.62,0) 5(10.16,0) 6(12.7,0)
  silkscreen extent -1.27,-1.27 13.97,1.27
IDC2.54-V20D [mm]
  rect 1.65x1.65 hole 0.889: 1(-11.43,-1.27)
  round 1.65 hole 0.889: 2(-11.43,1.27) 3(-8.89,-1.27) 4(-8.89,1.27) 5(-6.35,-1.27) 6(-6.35,1.27) 7(-3.81,-1.27) 8(-3.81,1.27) 9(-1.27,-1.27) 10(-1.27,1.27) 11(1.27,-1.27) 12(1.27,1.27) 13(3.81,-1.27) 14(3.81,1.27) 15(6.35,-1.27) 16(6.35,1.27) 17(8.89,-1.27) 18(8.89,1.27) 19(11.43,-1.27) 20(11.43,1.27)
  silkscreen extent -16.51,-5.37 16.51,4.6
LED2013 [mm]
  rect 1.3x1.6 smd: 1(0.95,0) 2(-0.95,0)
  silkscreen extent -2.13,-1.15 2,1.15
QFP40P2000X2000-176 [mm] "QFP; 176 Leads; Body 20 x 20 mm; Pitch 0.4 mm"
  rect 1.6x0.25 smd: 1(-10.6,8.6) 2(-10.6,8.2) 3(-10.6,7.8) 4(-10.6,7.4) 5(-10.6,7) 6(-10.6,6.6) 7(-10.6,6.2) 8(-10.6,5.8) 9(-10.6,5.4) 10(-10.6,5) 11(-10.6,4.6) 12(-10.6,4.2) 13(-10.6,3.8) 14(-10.6,3.4) 15(-10.6,3) 16(-10.6,2.6) 17(-10.6,2.2) 18(-10.6,1.8) 19(-10.6,1.4) 20(-10.6,1) 21(-10.6,0.6) 22(-10.6,0.2) 23(-10.6,-0.2) 24(-10.6,-0.6) 25(-10.6,-1) 26(-10.6,-1.4) 27(-10.6,-1.8) 28(-10.6,-2.2) 29(-10.6,-2.6) 30(-10.6,-3) 31(-10.6,-3.4) 32(-10.6,-3.8) 33(-10.6,-4.2) 34(-10.6,-4.6) 35(-10.6,-5) 36(-10.6,-5.4) 37(-10.6,-5.8) 38(-10.6,-6.2) 39(-10.6,-6.6) 40(-10.6,-7) 41(-10.6,-7.4) 42(-10.6,-7.8) 43(-10.6,-8.2) 44(-10.6,-8.6) 89(10.6,-8.6) 90(10.6,-8.2) 91(10.6,-7.8) 92(10.6,-7.4) 93(10.6,-7) 94(10.6,-6.6) 95(10.6,-6.2) 96(10.6,-5.8) 97(10.6,-5.4) 98(10.6,-5) 99(10.6,-4.6) 100(10.6,-4.2) 101(10.6,-3.8) 102(10.6,-3.4) 103(10.6,-3) 104(10.6,-2.6) 105(10.6,-2.2) 106(10.6,-1.8) 107(10.6,-1.4) 108(10.6,-1) 109(10.6,-0.6) 110(10.6,-0.2) 111(10.6,0.2) 112(10.6,0.6) 113(10.6,1) 114(10.6,1.4) 115(10.6,1.8) 116(10.6,2.2) 117(10.6,2.6) 118(10.6,3) 119(10.6,3.4) 120(10.6,3.8) 121(10.6,4.2) 122(10.6,4.6) 123(10.6,5) 124(10.6,5.4) 125(10.6,5.8) 126(10.6,6.2) 127(10.6,6.6) 128(10.6,7) 129(10.6,7.4) 130(10.6,7.8) 131(10.6,8.2) 132(10.6,8.6)
  rect 0.25x1.6 smd: 45(-8.6,-10.6) 46(-8.2,-10.6) 47(-7.8,-10.6) 48(-7.4,-10.6) 49(-7,-10.6) 50(-6.6,-10.6) 51(-6.2,-10.6) 52(-5.8,-10.6) 53(-5.4,-10.6) 54(-5,-10.6) 55(-4.6,-10.6) 56(-4.2,-10.6) 57(-3.8,-10.6) 58(-3.4,-10.6) 59(-3,-10.6) 60(-2.6,-10.6) 61(-2.2,-10.6) 62(-1.8,-10.6) 63(-1.4,-10.6) 64(-1,-10.6) 65(-0.6,-10.6) 66(-0.2,-10.6) 67(0.2,-10.6) 68(0.6,-10.6) 69(1,-10.6) 70(1.4,-10.6) 71(1.8,-10.6) 72(2.2,-10.6) 73(2.6,-10.6) 74(3,-10.6) 75(3.4,-10.6) 76(3.8,-10.6) 77(4.2,-10.6) 78(4.6,-10.6) 79(5,-10.6) 80(5.4,-10.6) 81(5.8,-10.6) 82(6.2,-10.6) 83(6.6,-10.6) 84(7,-10.6) 85(7.4,-10.6) 86(7.8,-10.6) 87(8.2,-10.6) 88(8.6,-10.6) 133(8.6,10.6) 134(8.2,10.6) 135(7.8,10.6) 136(7.4,10.6) 137(7,10.6) 138(6.6,10.6) 139(6.2,10.6) 140(5.8,10.6) 141(5.4,10.6) 142(5,10.6) 143(4.6,10.6) 144(4.2,10.6) 145(3.8,10.6) 146(3.4,10.6) 147(3,10.6) 148(2.6,10.6) 149(2.2,10.6) 150(1.8,10.6) 151(1.4,10.6) 152(1,10.6) 153(0.6,10.6) 154(0.2,10.6) 155(-0.2,10.6) 156(-0.6,10.6) 157(-1,10.6) 158(-1.4,10.6) 159(-1.8,10.6) 160(-2.2,10.6) 161(-2.6,10.6) 162(-3,10.6) 163(-3.4,10.6) 164(-3.8,10.6) 165(-4.2,10.6) 166(-4.6,10.6) 167(-5,10.6) 168(-5.4,10.6) 169(-5.8,10.6) 170(-6.2,10.6) 171(-6.6,10.6) 172(-7,10.6) 173(-7.4,10.6) 174(-7.8,10.6) 175(-8.2,10.6) 176(-8.6,10.6)
  silkscreen extent -12.07,-9.4 9.4,9.4
RESC1005 [mm]
  rect 0.6x0.5 smd: 1(0.5,0) 2(-0.5,0)
  silkscreen extent -0.1,-0.2 0.1,0.2
RESC2012 [mm]
  rect 1.3x1.5 smd: 1(-0.95,0) 2(0.95,0)
SOP127P600-8 [mm]
  rect 0.6x2.2 smd: 1(-1.905,-2.6) 2(-0.635,-2.6) 3(0.635,-2.6) 4(1.905,-2.6) 5(1.905,2.6) 6(0.635,2.6) 7(-0.635,2.6) 8(-1.905,2.6)
  silkscreen extent -2.88,-2.72 2.5,1.1
SOT95P230-3 [mm]
  rect 0.9x0.95 smd: 1(-0.95,-1.25) 2(0.95,-1.25) 3(0,1.25)
  silkscreen extent -2.07,-1.37 1.3,1.25
SOT95P280-5 [mm] "SOT-23/SC-74A; 5 Leads; Body 3.1 x 3 mm, inc. leads (LxW max)"
  rect 0.55x1.45 smd: 1(-0.95,-1.075) 2(0,-1.075) 3(0.95,-1.075) 4(0.95,1.075) 5(-0.95,1.075)
  silkscreen extent -1.57,-1.35 1.55,0.9
TestPin [mil] "SingleTest Pin"
  round 60 hole 35: 1(0,0)
TO254P1435-4 [mm]
  rect 1x3.4 smd: 1(0,0) 2(2.54,0) 3(5.08,0)
  rect 10.25x8.9 smd: 4(2.54,10.45)
  silkscreen extent -3.1,-0.13 8.2,14.8
TSOP65P638-16 [mm]
  rect 0.3x1.65 smd: 1(-2.275,-2.775) 2(-1.625,-2.775) 3(-0.975,-2.775) 4(-0.325,-2.775) 5(0.325,-2.775) 6(0.975,-2.775) 7(1.625,-2.775) 8(2.275,-2.775) 9(2.275,2.775) 10(1.625,2.775) 11(0.975,2.775) 12(0.325,2.775) 13(-0.325,2.775) 14(-0.975,2.775) 15(-1.625,2.775) 16(-2.275,2.775)
  silkscreen extent -3.1,-2.9 2.55,1.55
TSOP80P1176-44 [mm]
  rect 0.45x1.4 smd: 1(-8.4,-5.7) 2(-7.6,-5.7) 3(-6.8,-5.7) 4(-6,-5.7) 5(-5.2,-5.7) 6(-4.4,-5.7) 7(-3.6,-5.7) 8(-2.8,-5.7) 9(-2,-5.7) 10(-1.2,-5.7) 11(-0.4,-5.7) 12(0.4,-5.7) 13(1.2,-5.7) 14(2,-5.7) 15(2.8,-5.7) 16(3.6,-5.7) 17(4.4,-5.7) 18(5.2,-5.7) 19(6,-5.7) 20(6.8,-5.7) 21(7.6,-5.7) 22(8.4,-5.7) 23(8.4,5.7) 24(7.6,5.7) 25(6.8,5.7) 26(6,5.7) 27(5.2,5.7) 28(4.4,5.7) 29(3.6,5.7) 30(2.8,5.7) 31(2,5.7) 32(1.2,5.7) 33(0.4,5.7) 34(-0.4,5.7) 35(-1.2,5.7) 36(-2,5.7) 37(-2.8,5.7) 38(-3.6,5.7) 39(-4.4,5.7) 40(-5.2,5.7) 41(-6,5.7) 42(-6.8,5.7) 43(-7.6,5.7) 44(-8.4,5.7)
  silkscreen extent -9.29,-5.7 9.26,4.45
